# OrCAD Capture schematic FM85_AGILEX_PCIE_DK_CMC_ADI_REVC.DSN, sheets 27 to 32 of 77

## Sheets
27 QSFPDD IO: size B
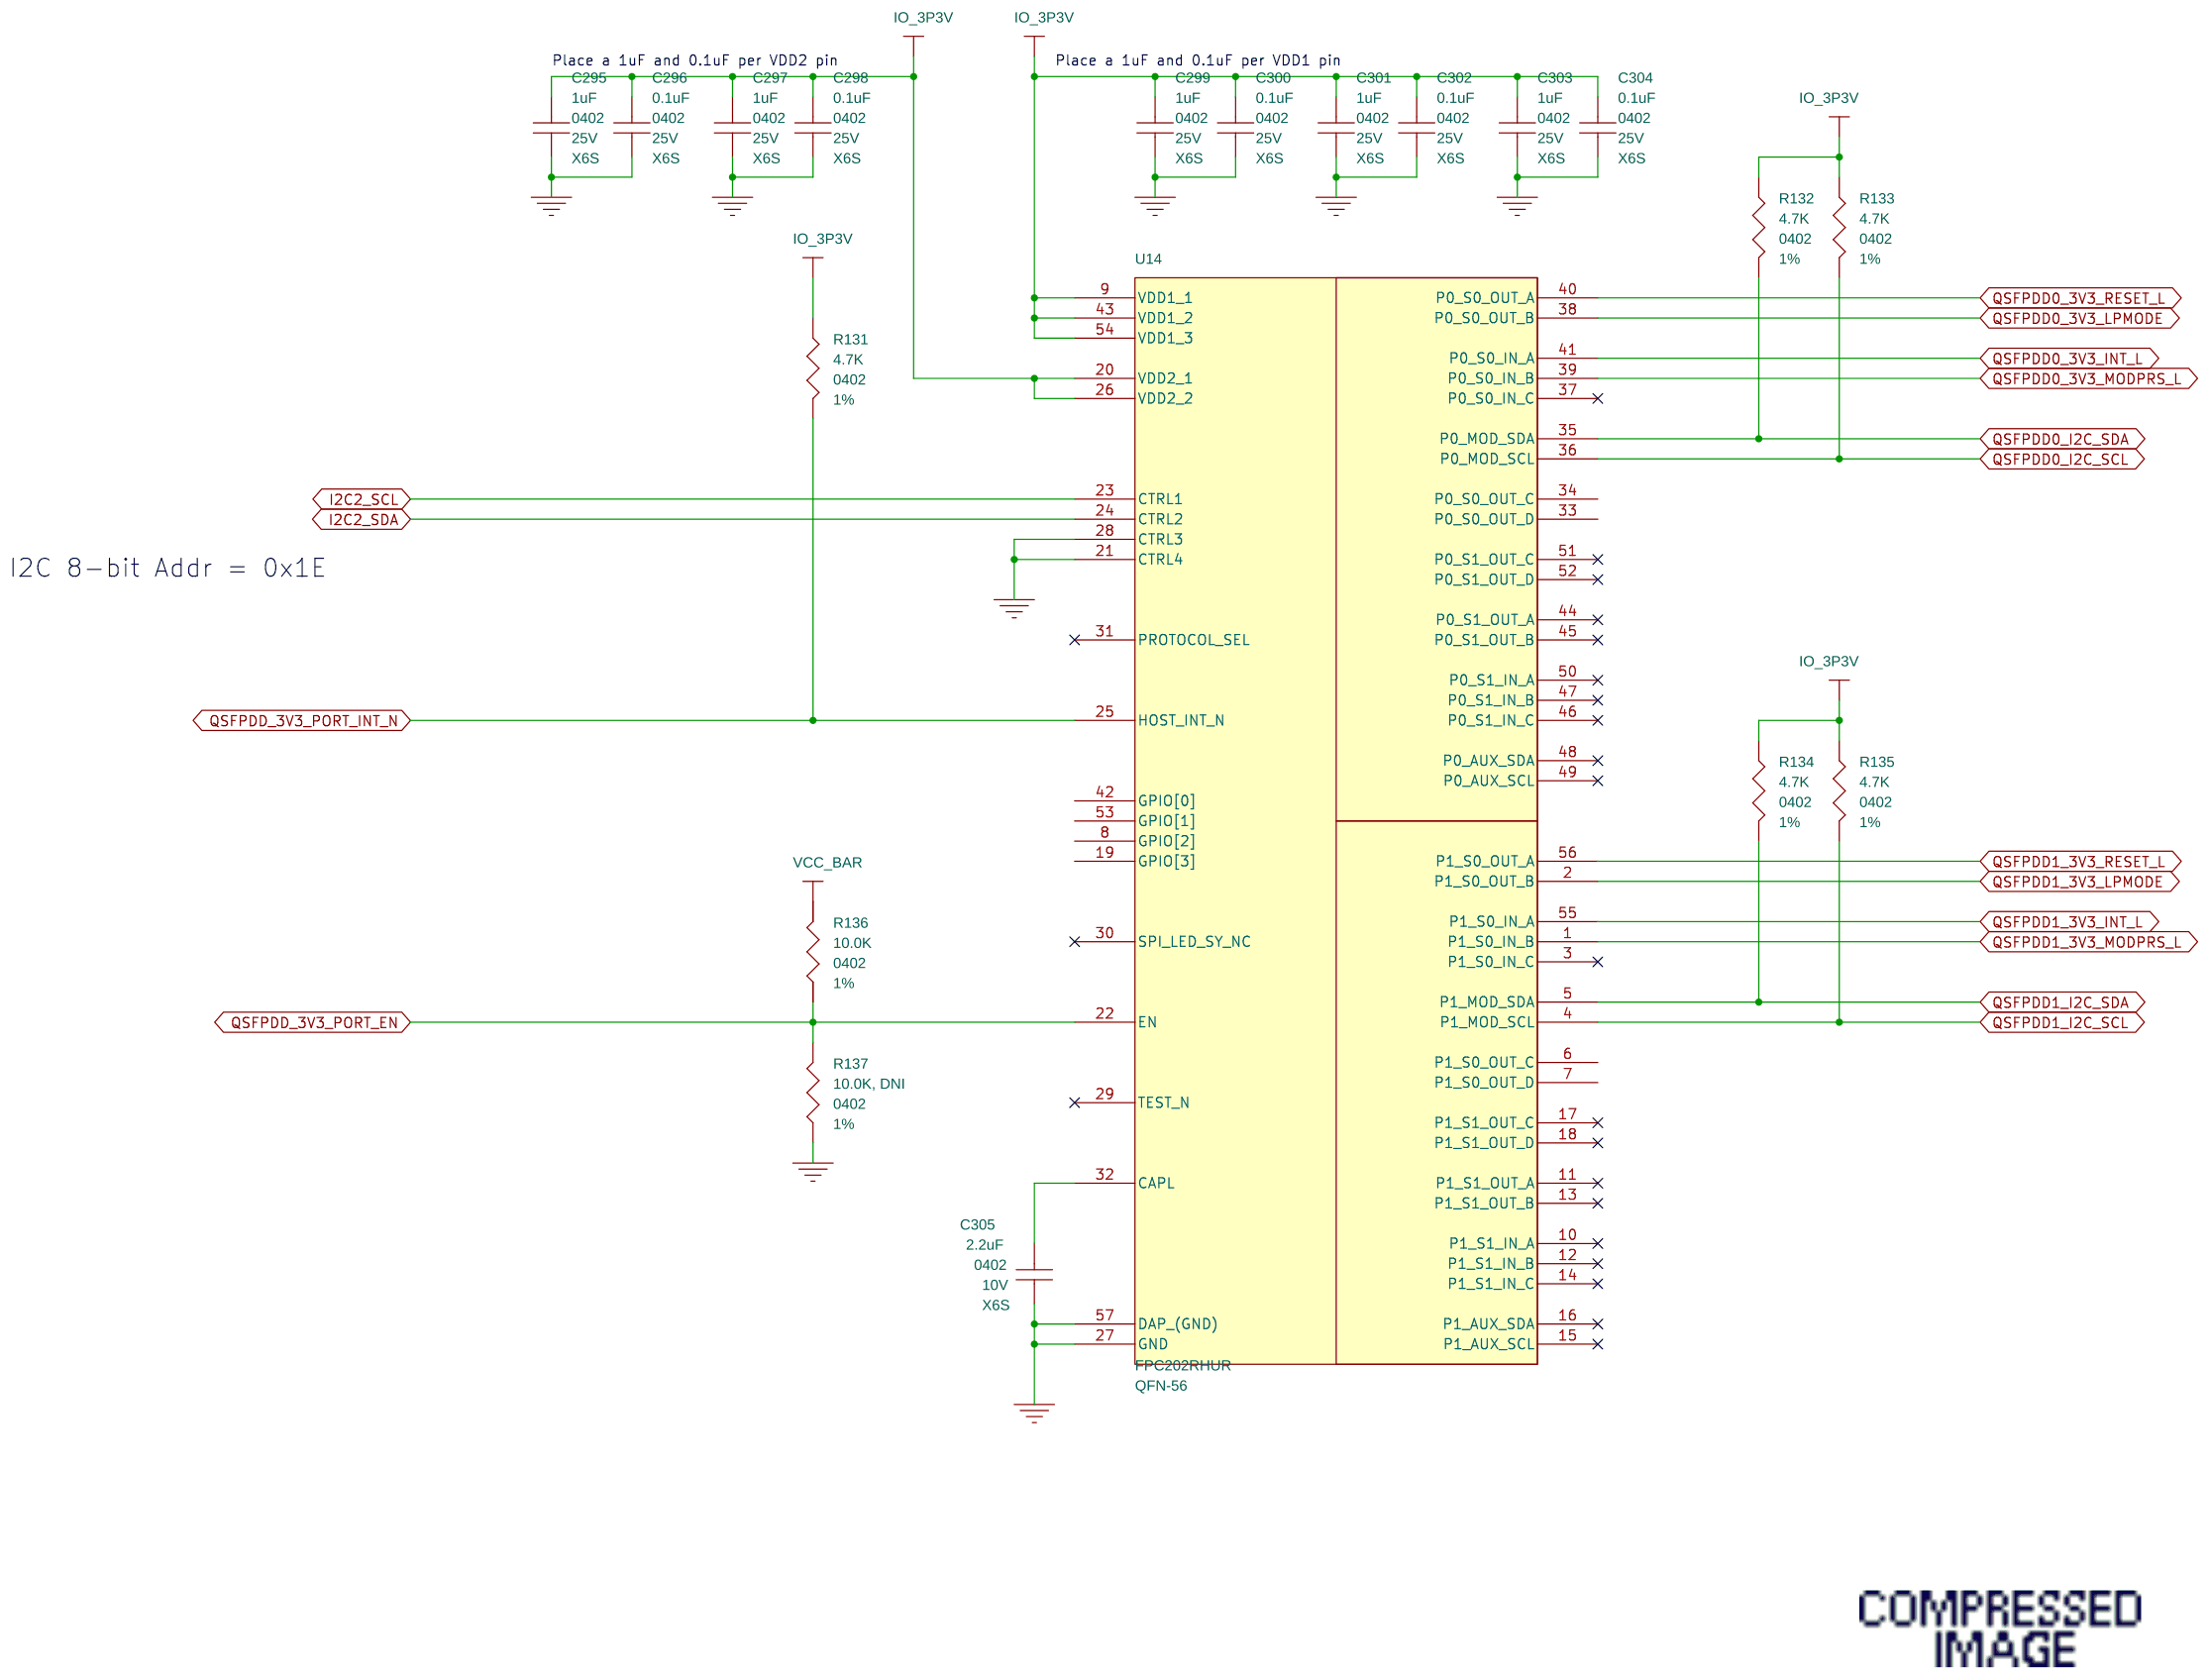
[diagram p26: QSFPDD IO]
28 FPGA BANK 12A: size B
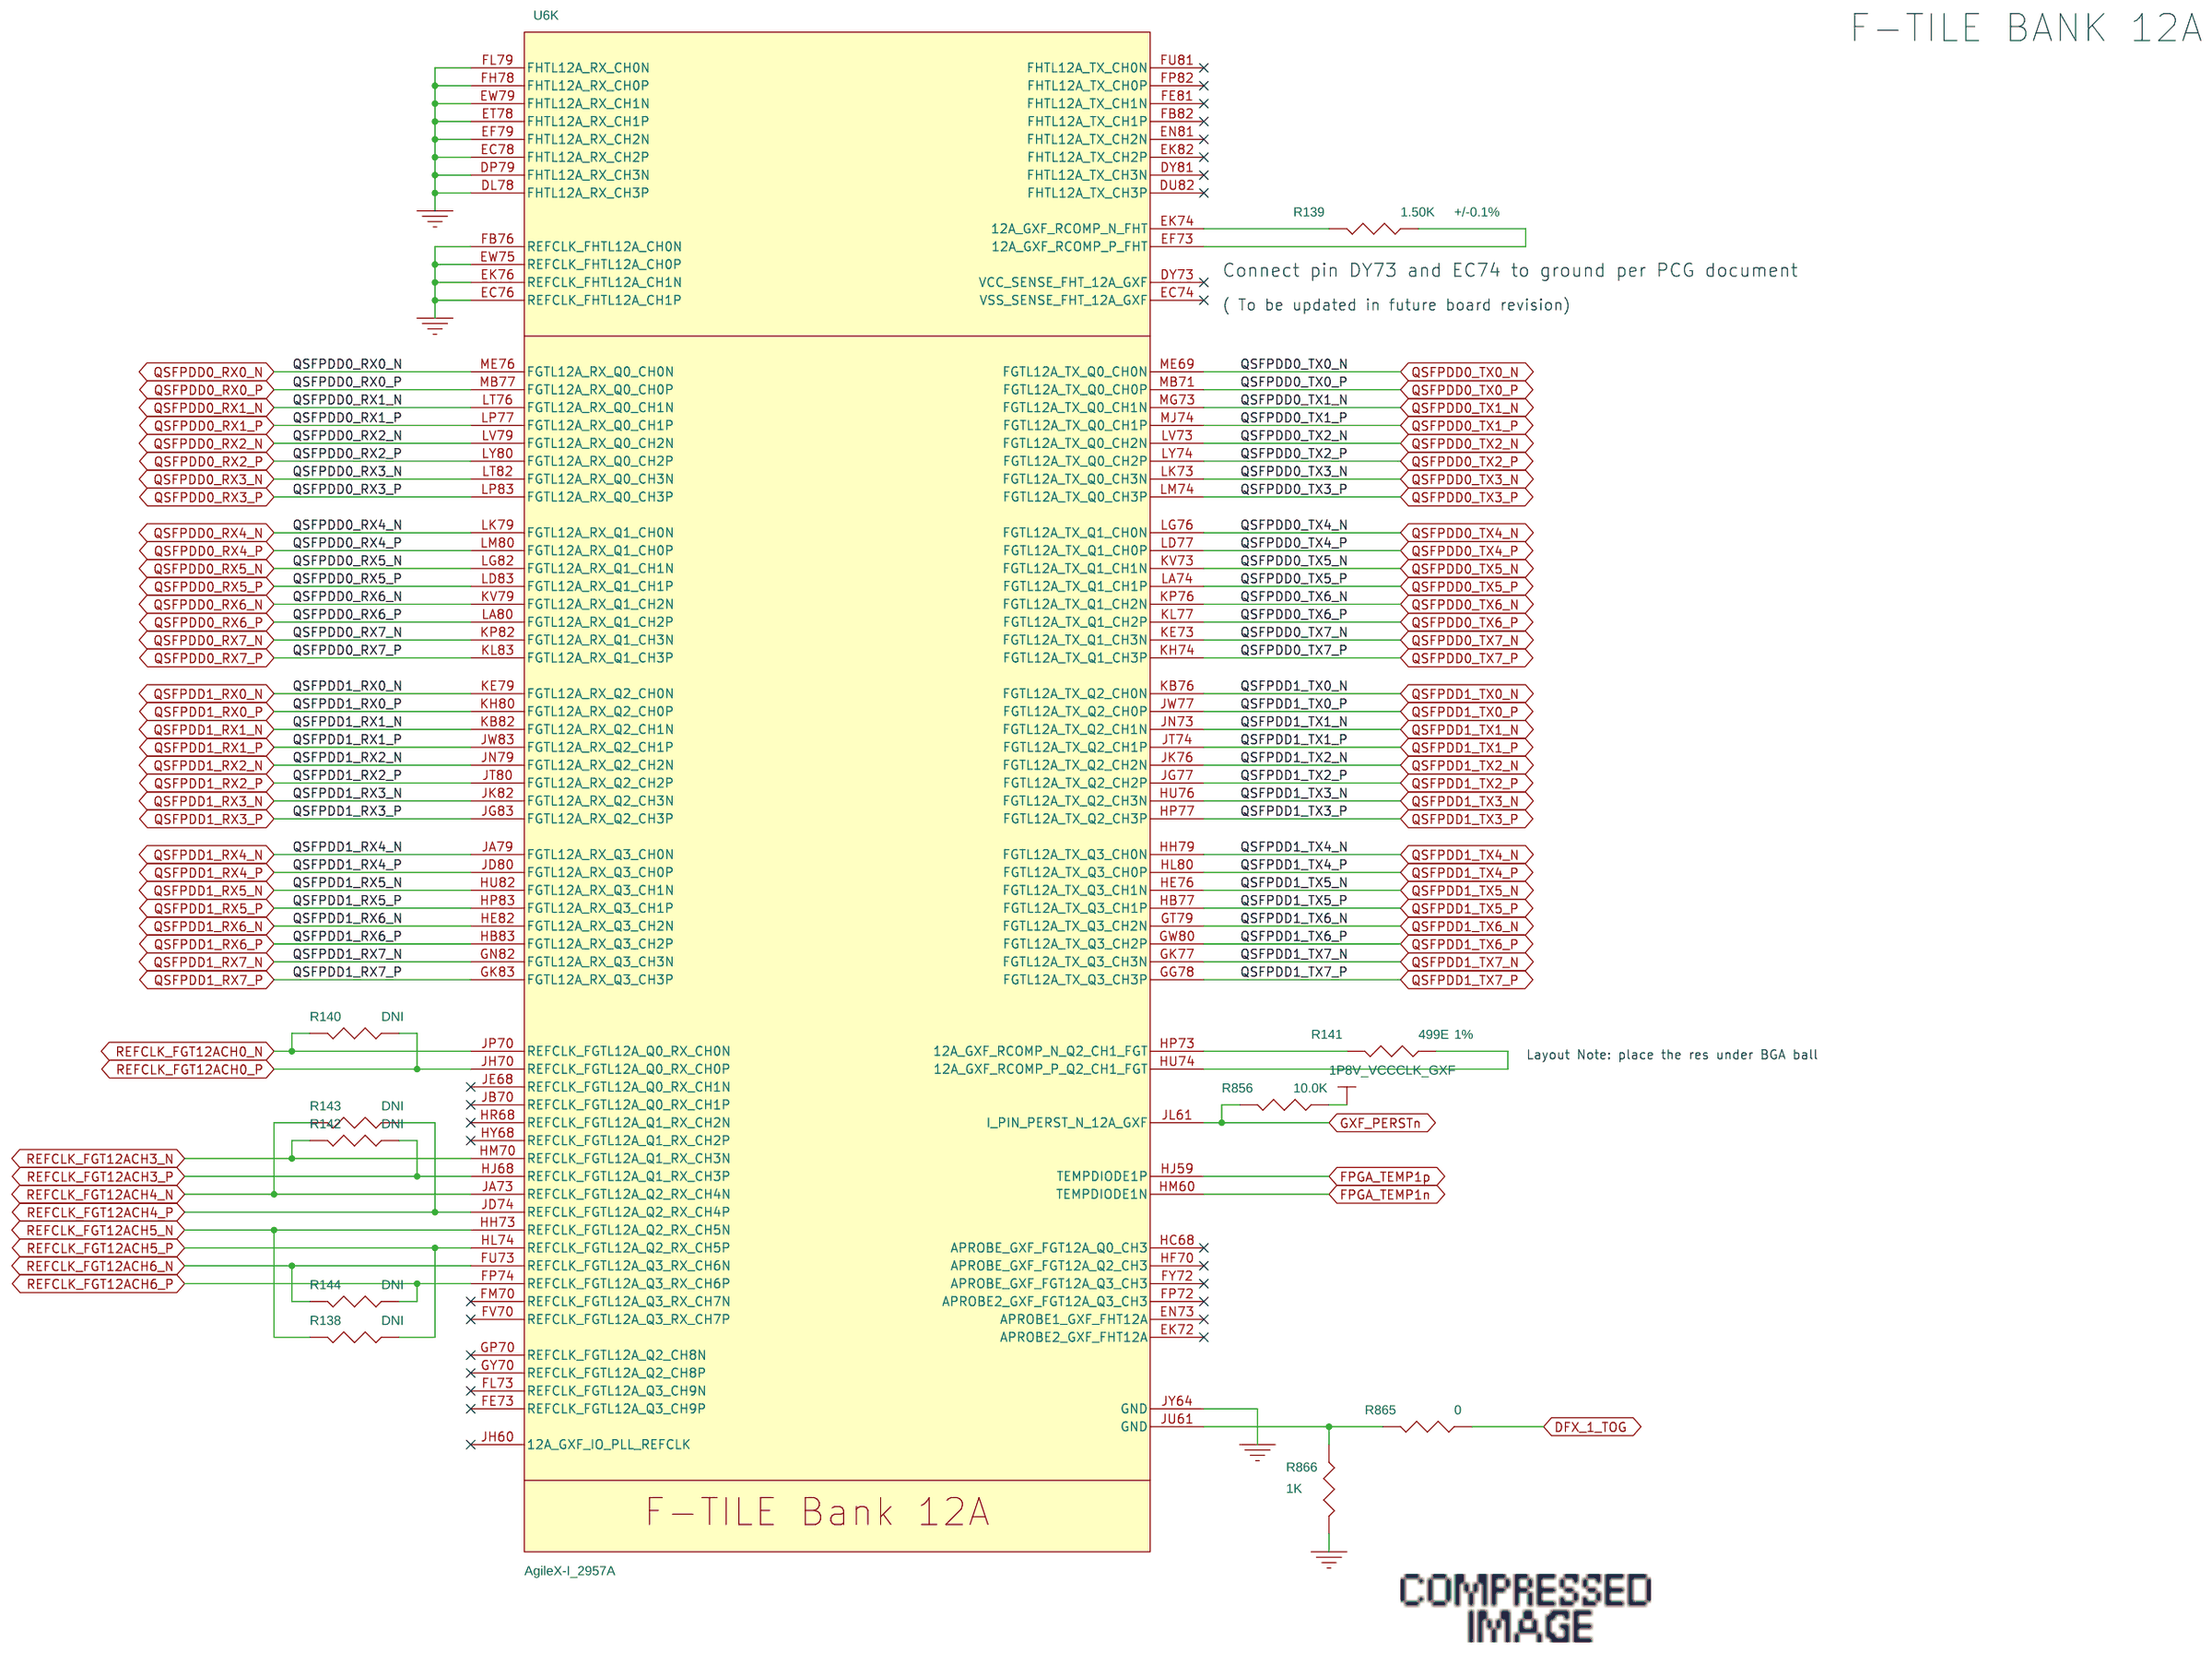
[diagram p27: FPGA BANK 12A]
29 FPGA BANK 12A DNU: size B
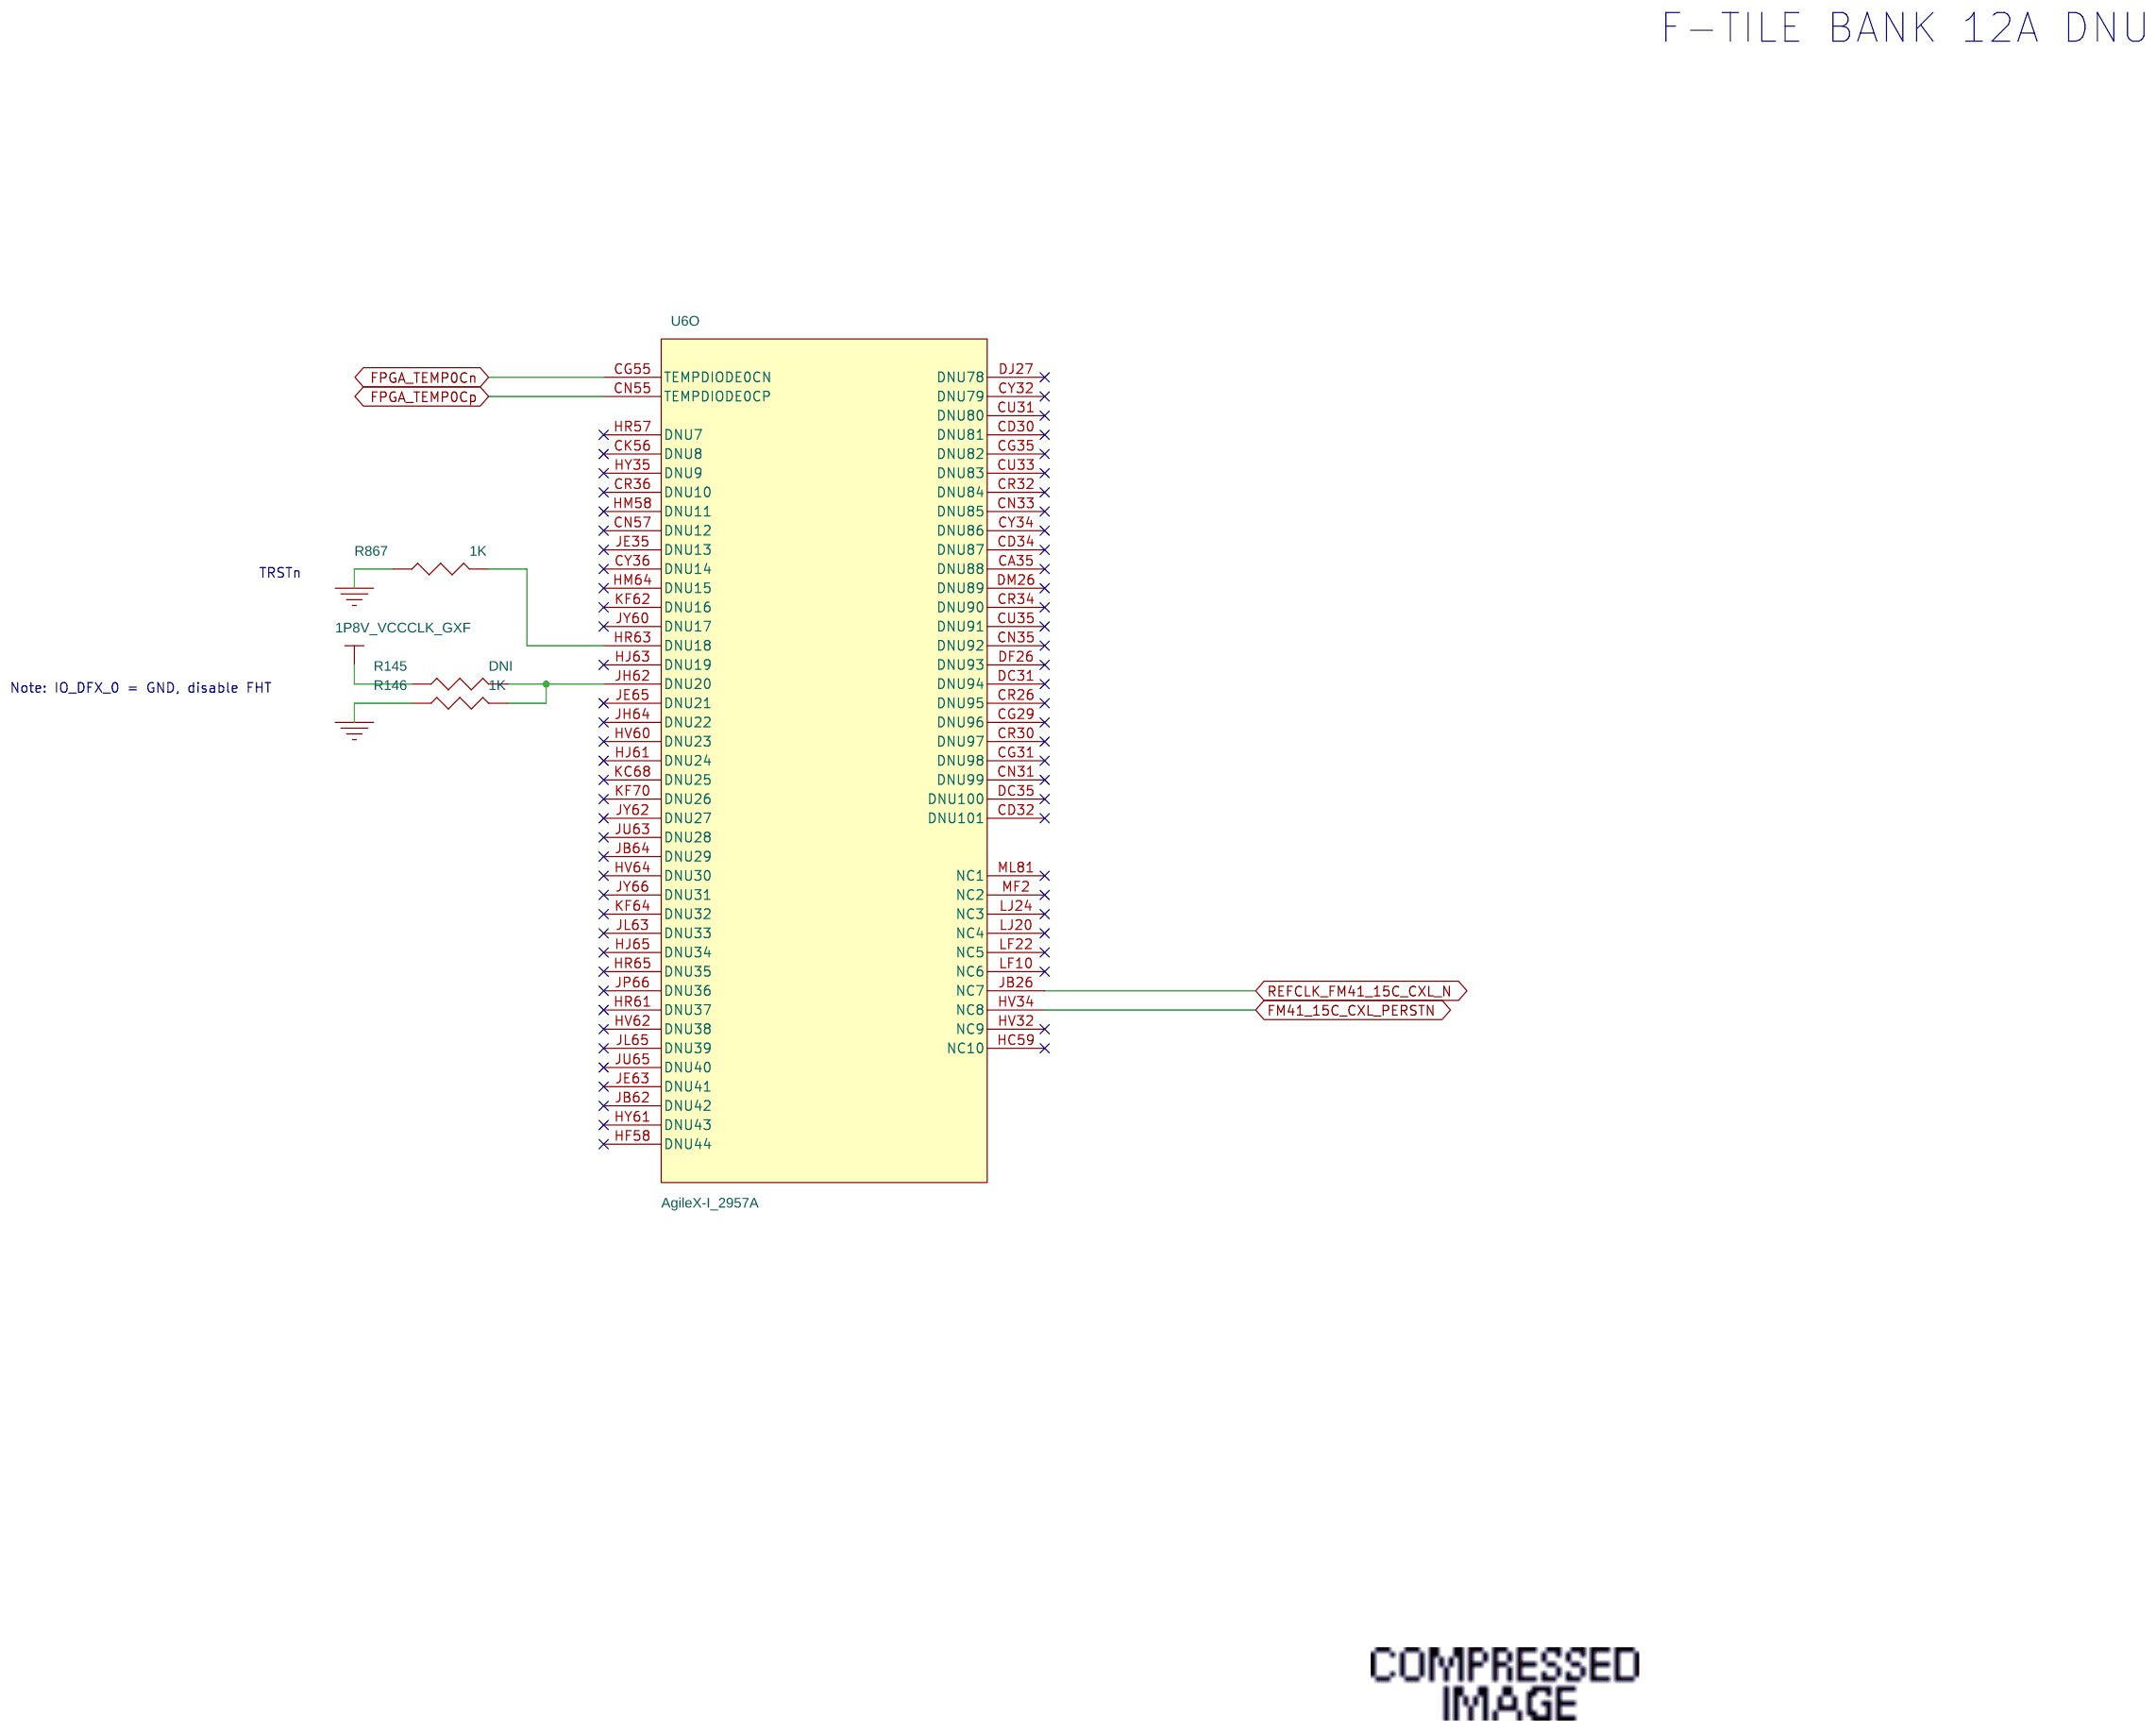
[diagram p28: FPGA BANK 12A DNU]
30 PCIe EP Edge Connector: size B
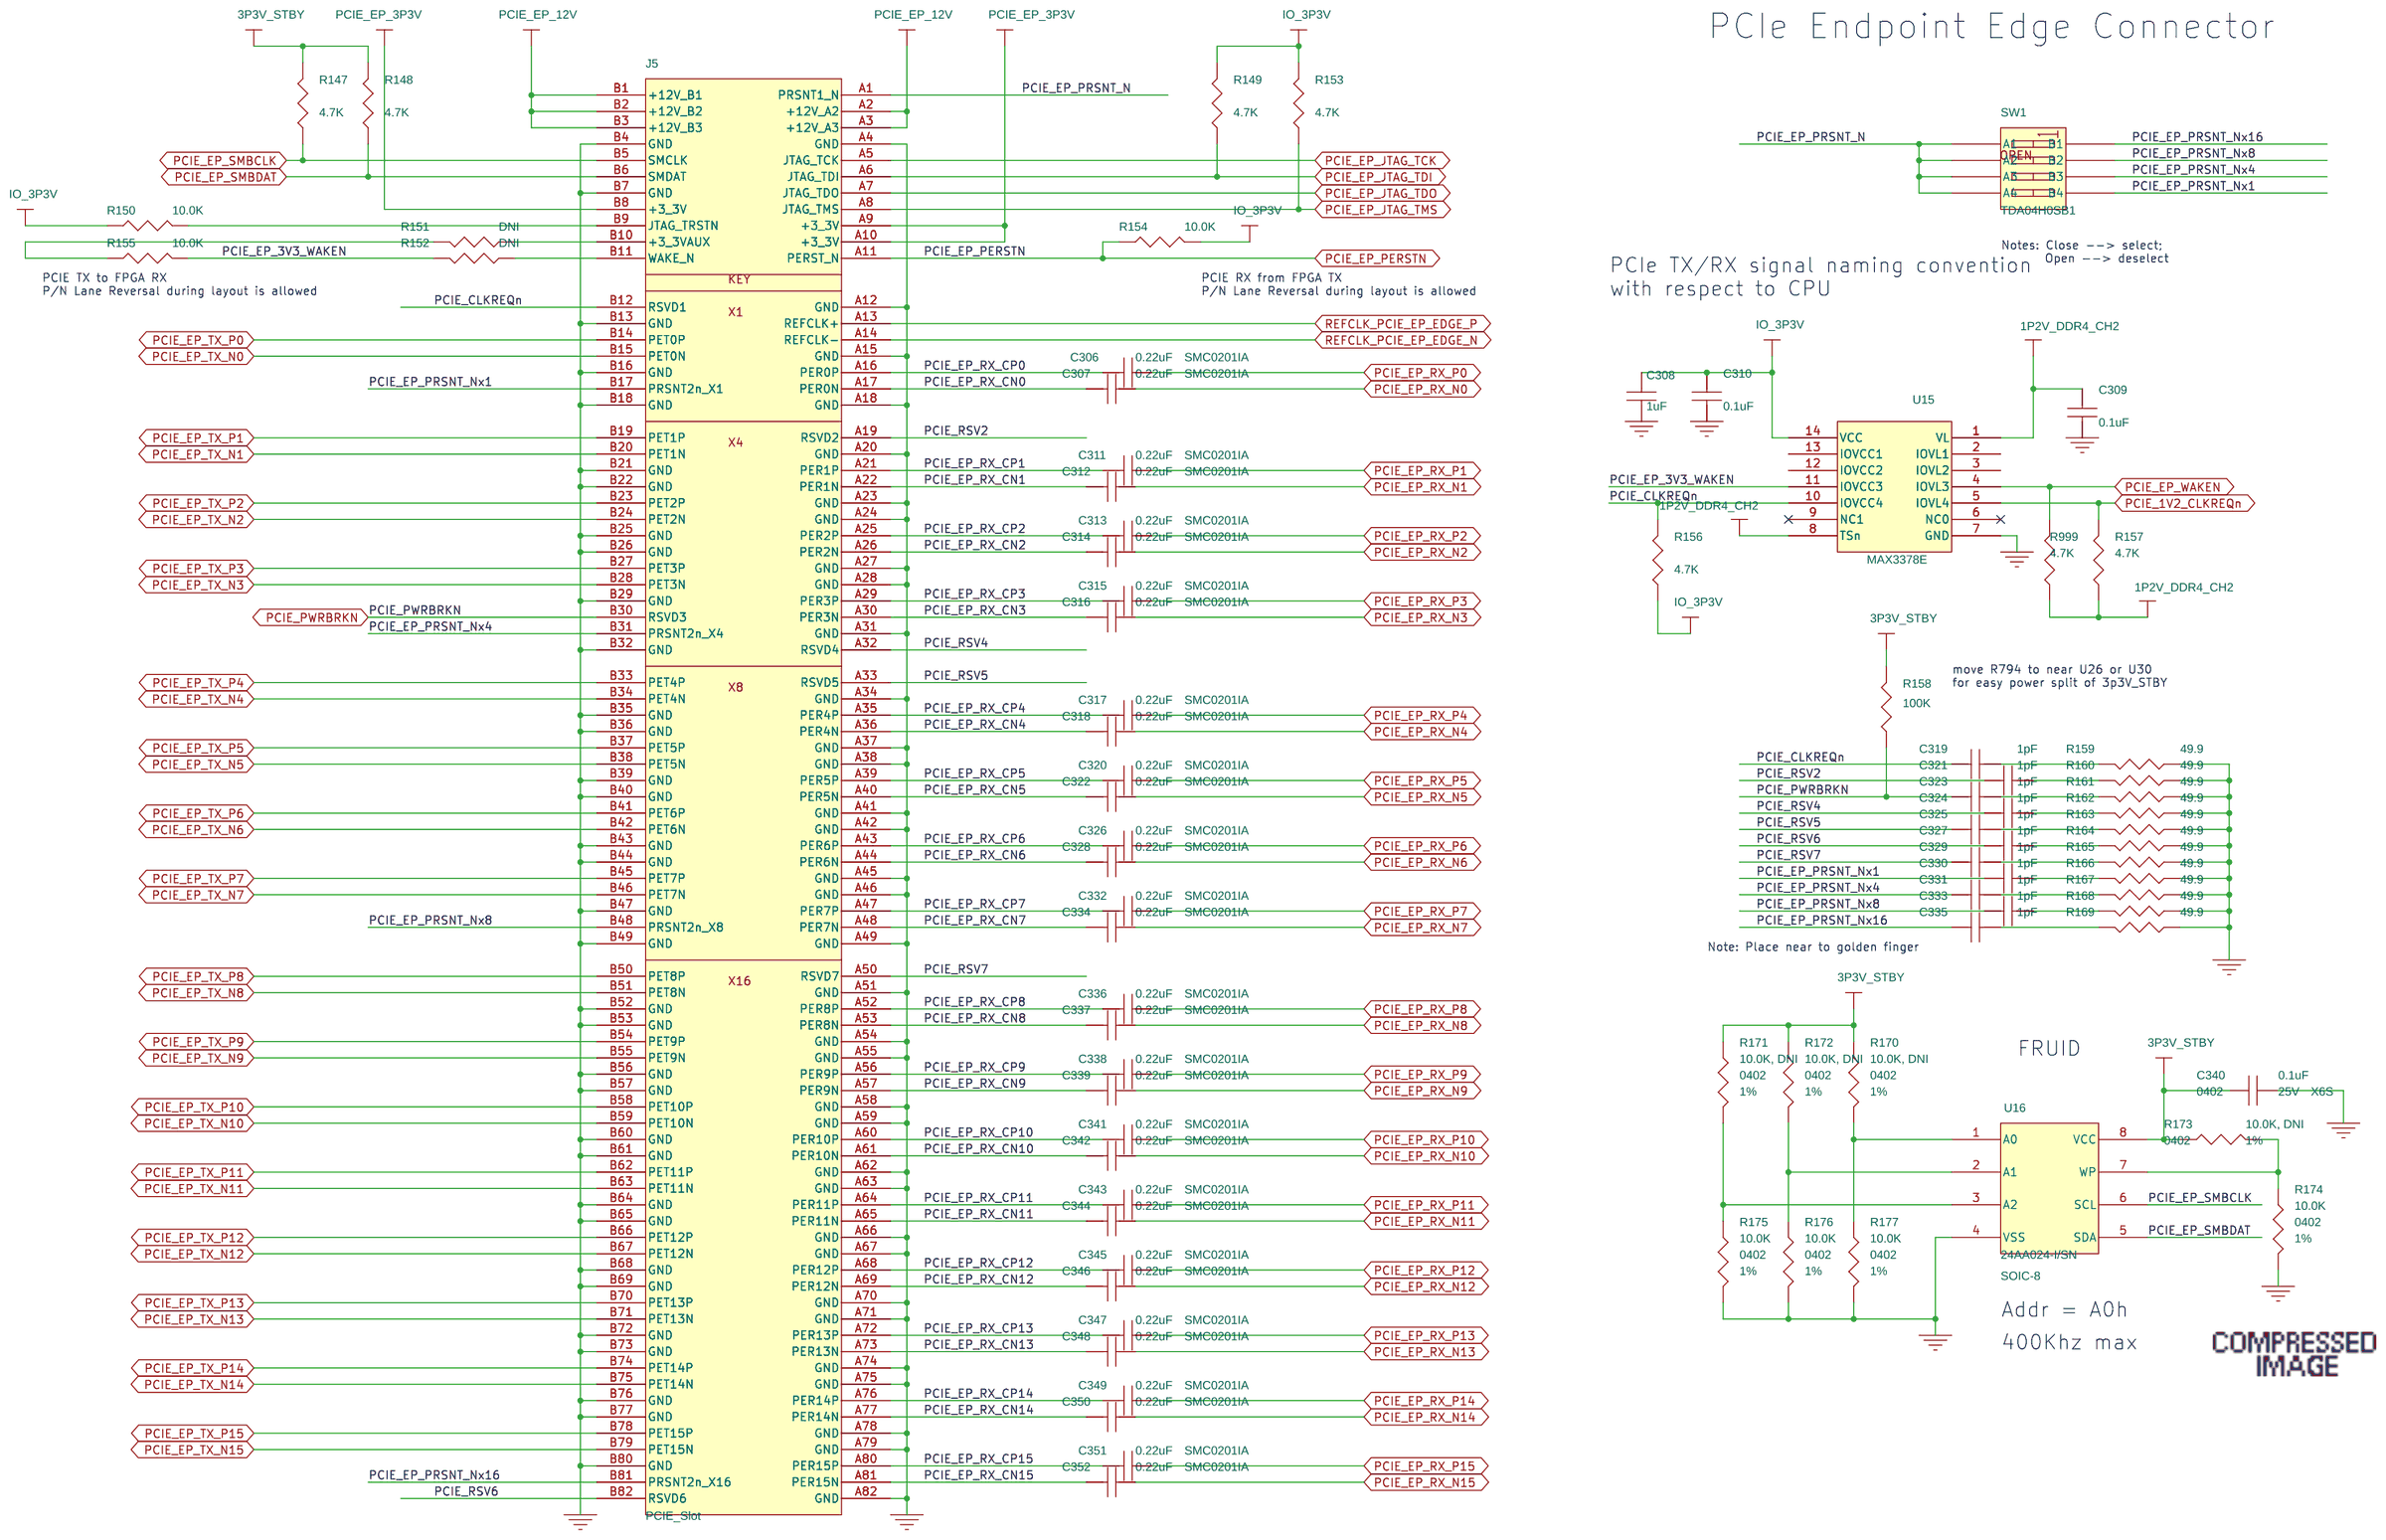
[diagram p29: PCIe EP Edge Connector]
31 FPGA BANK 14C: size B
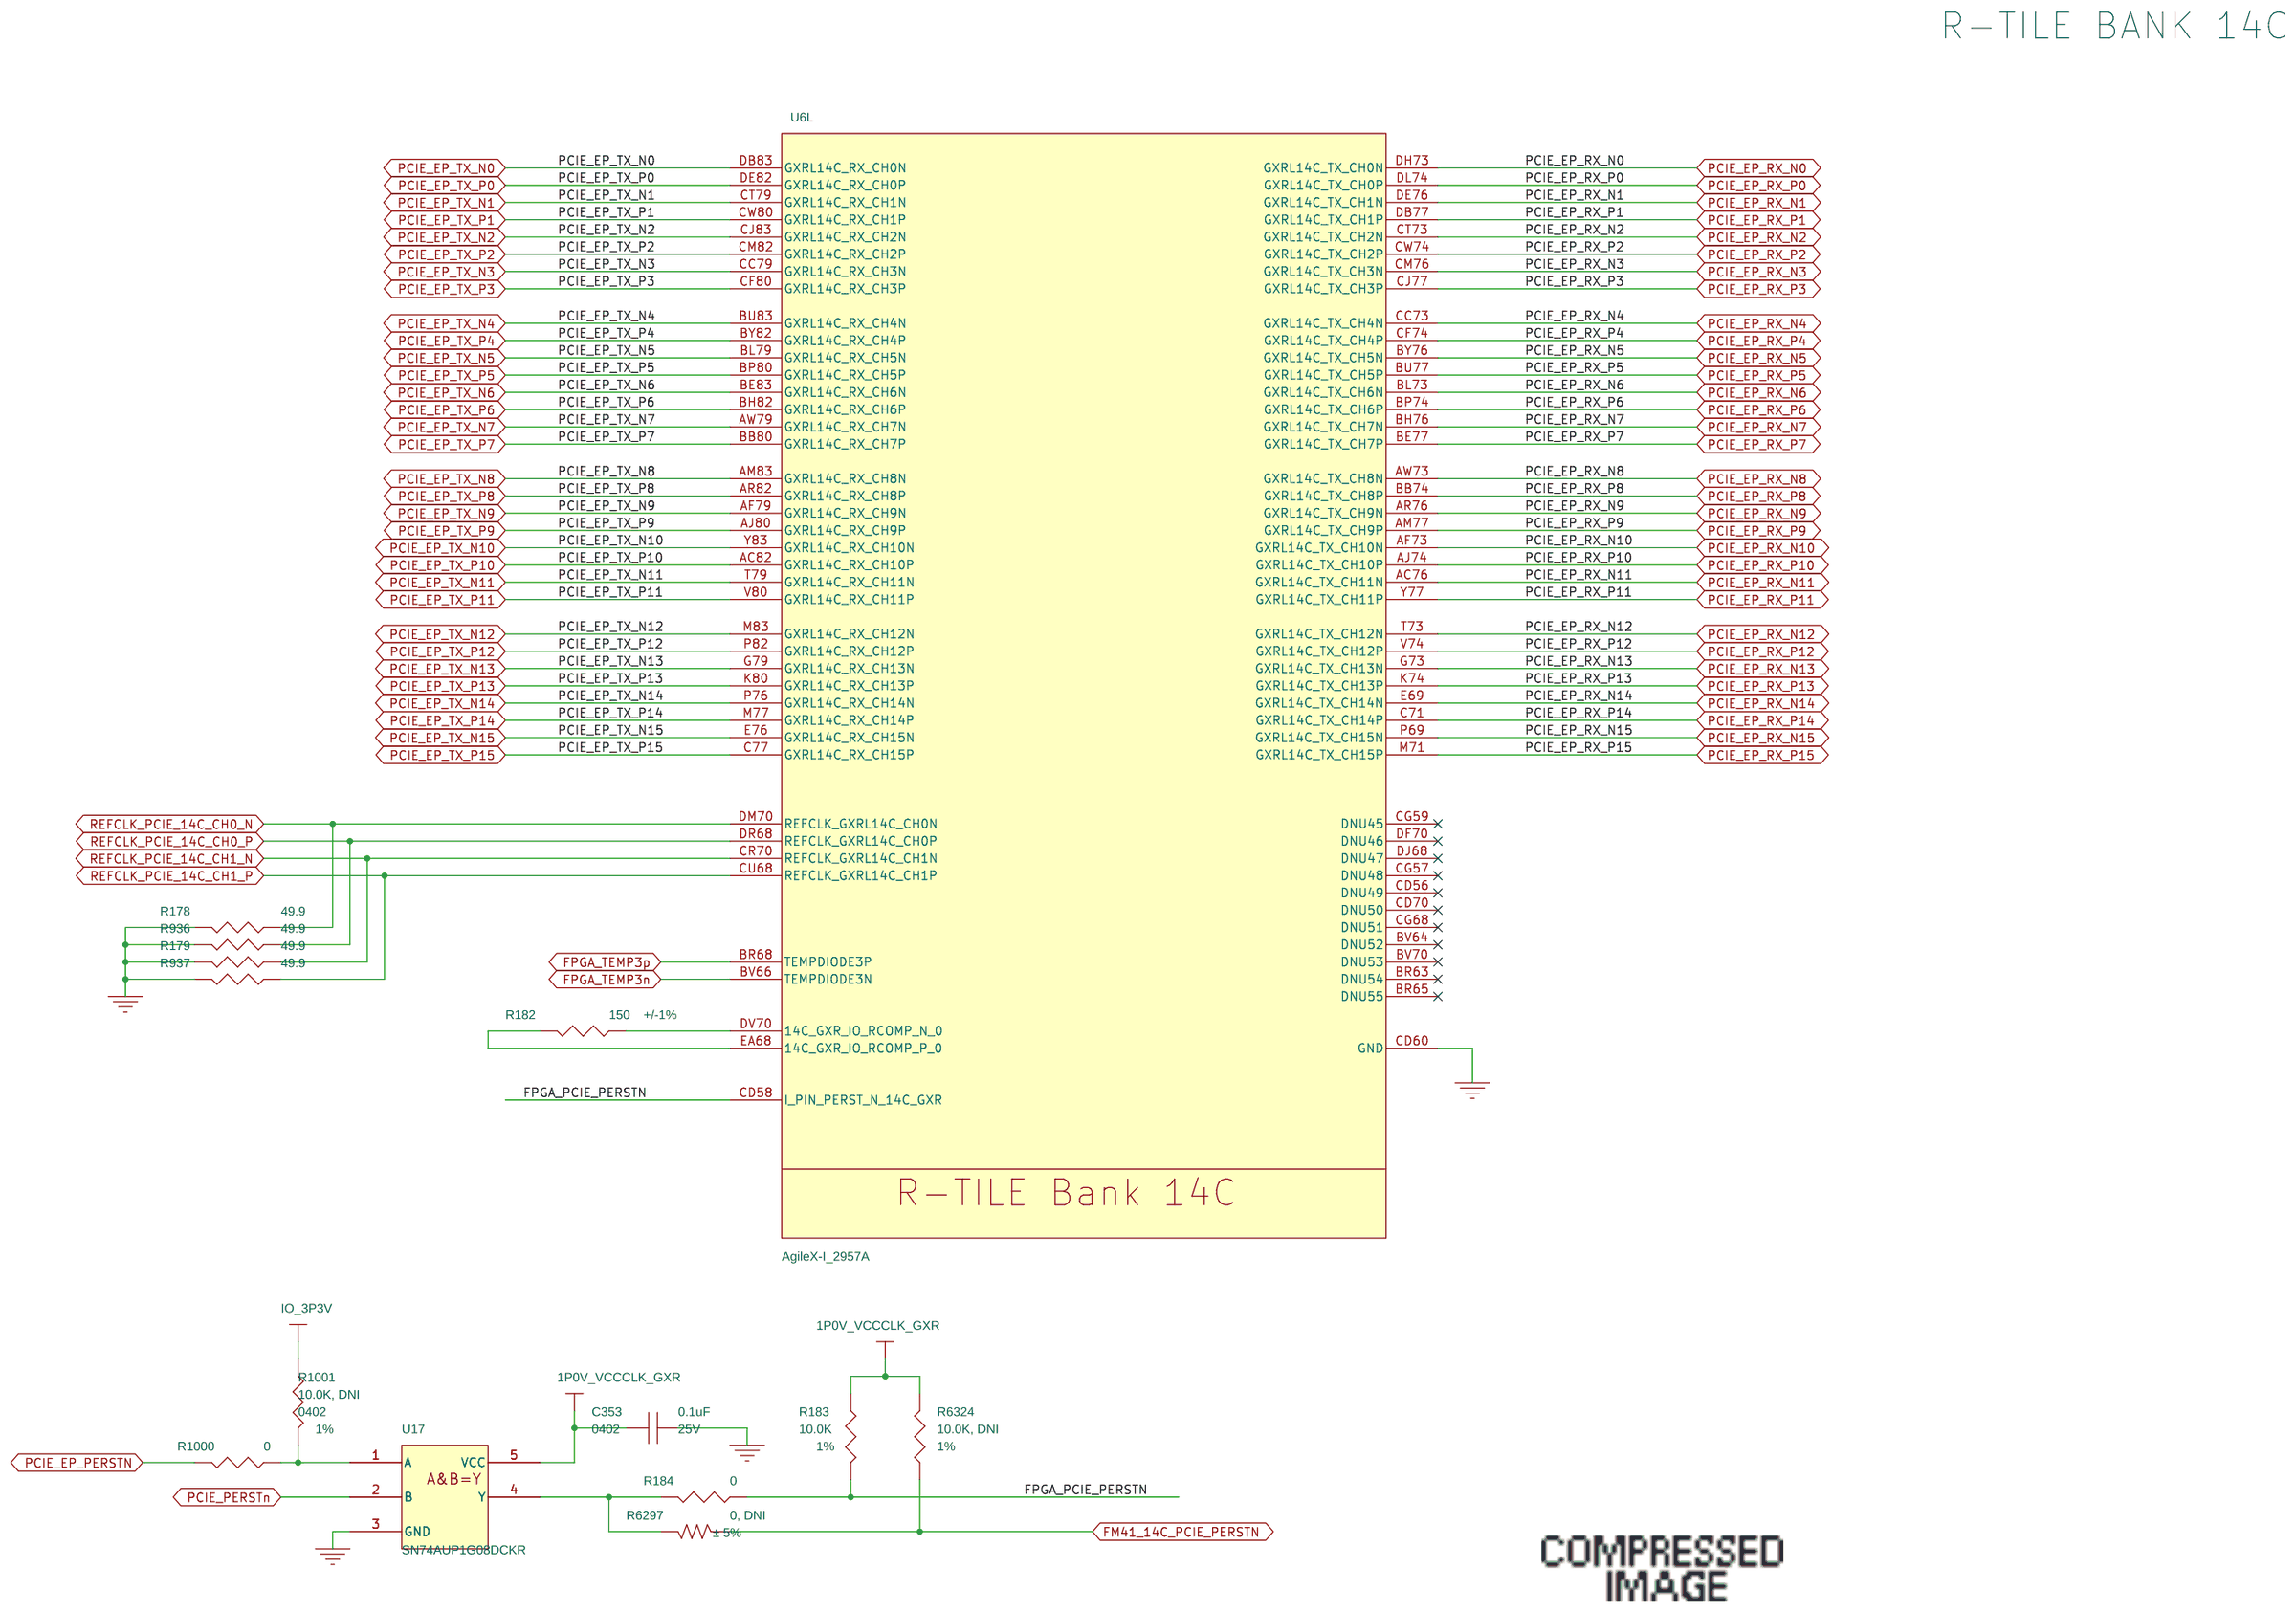
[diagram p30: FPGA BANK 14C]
32 CXL Connector: size B
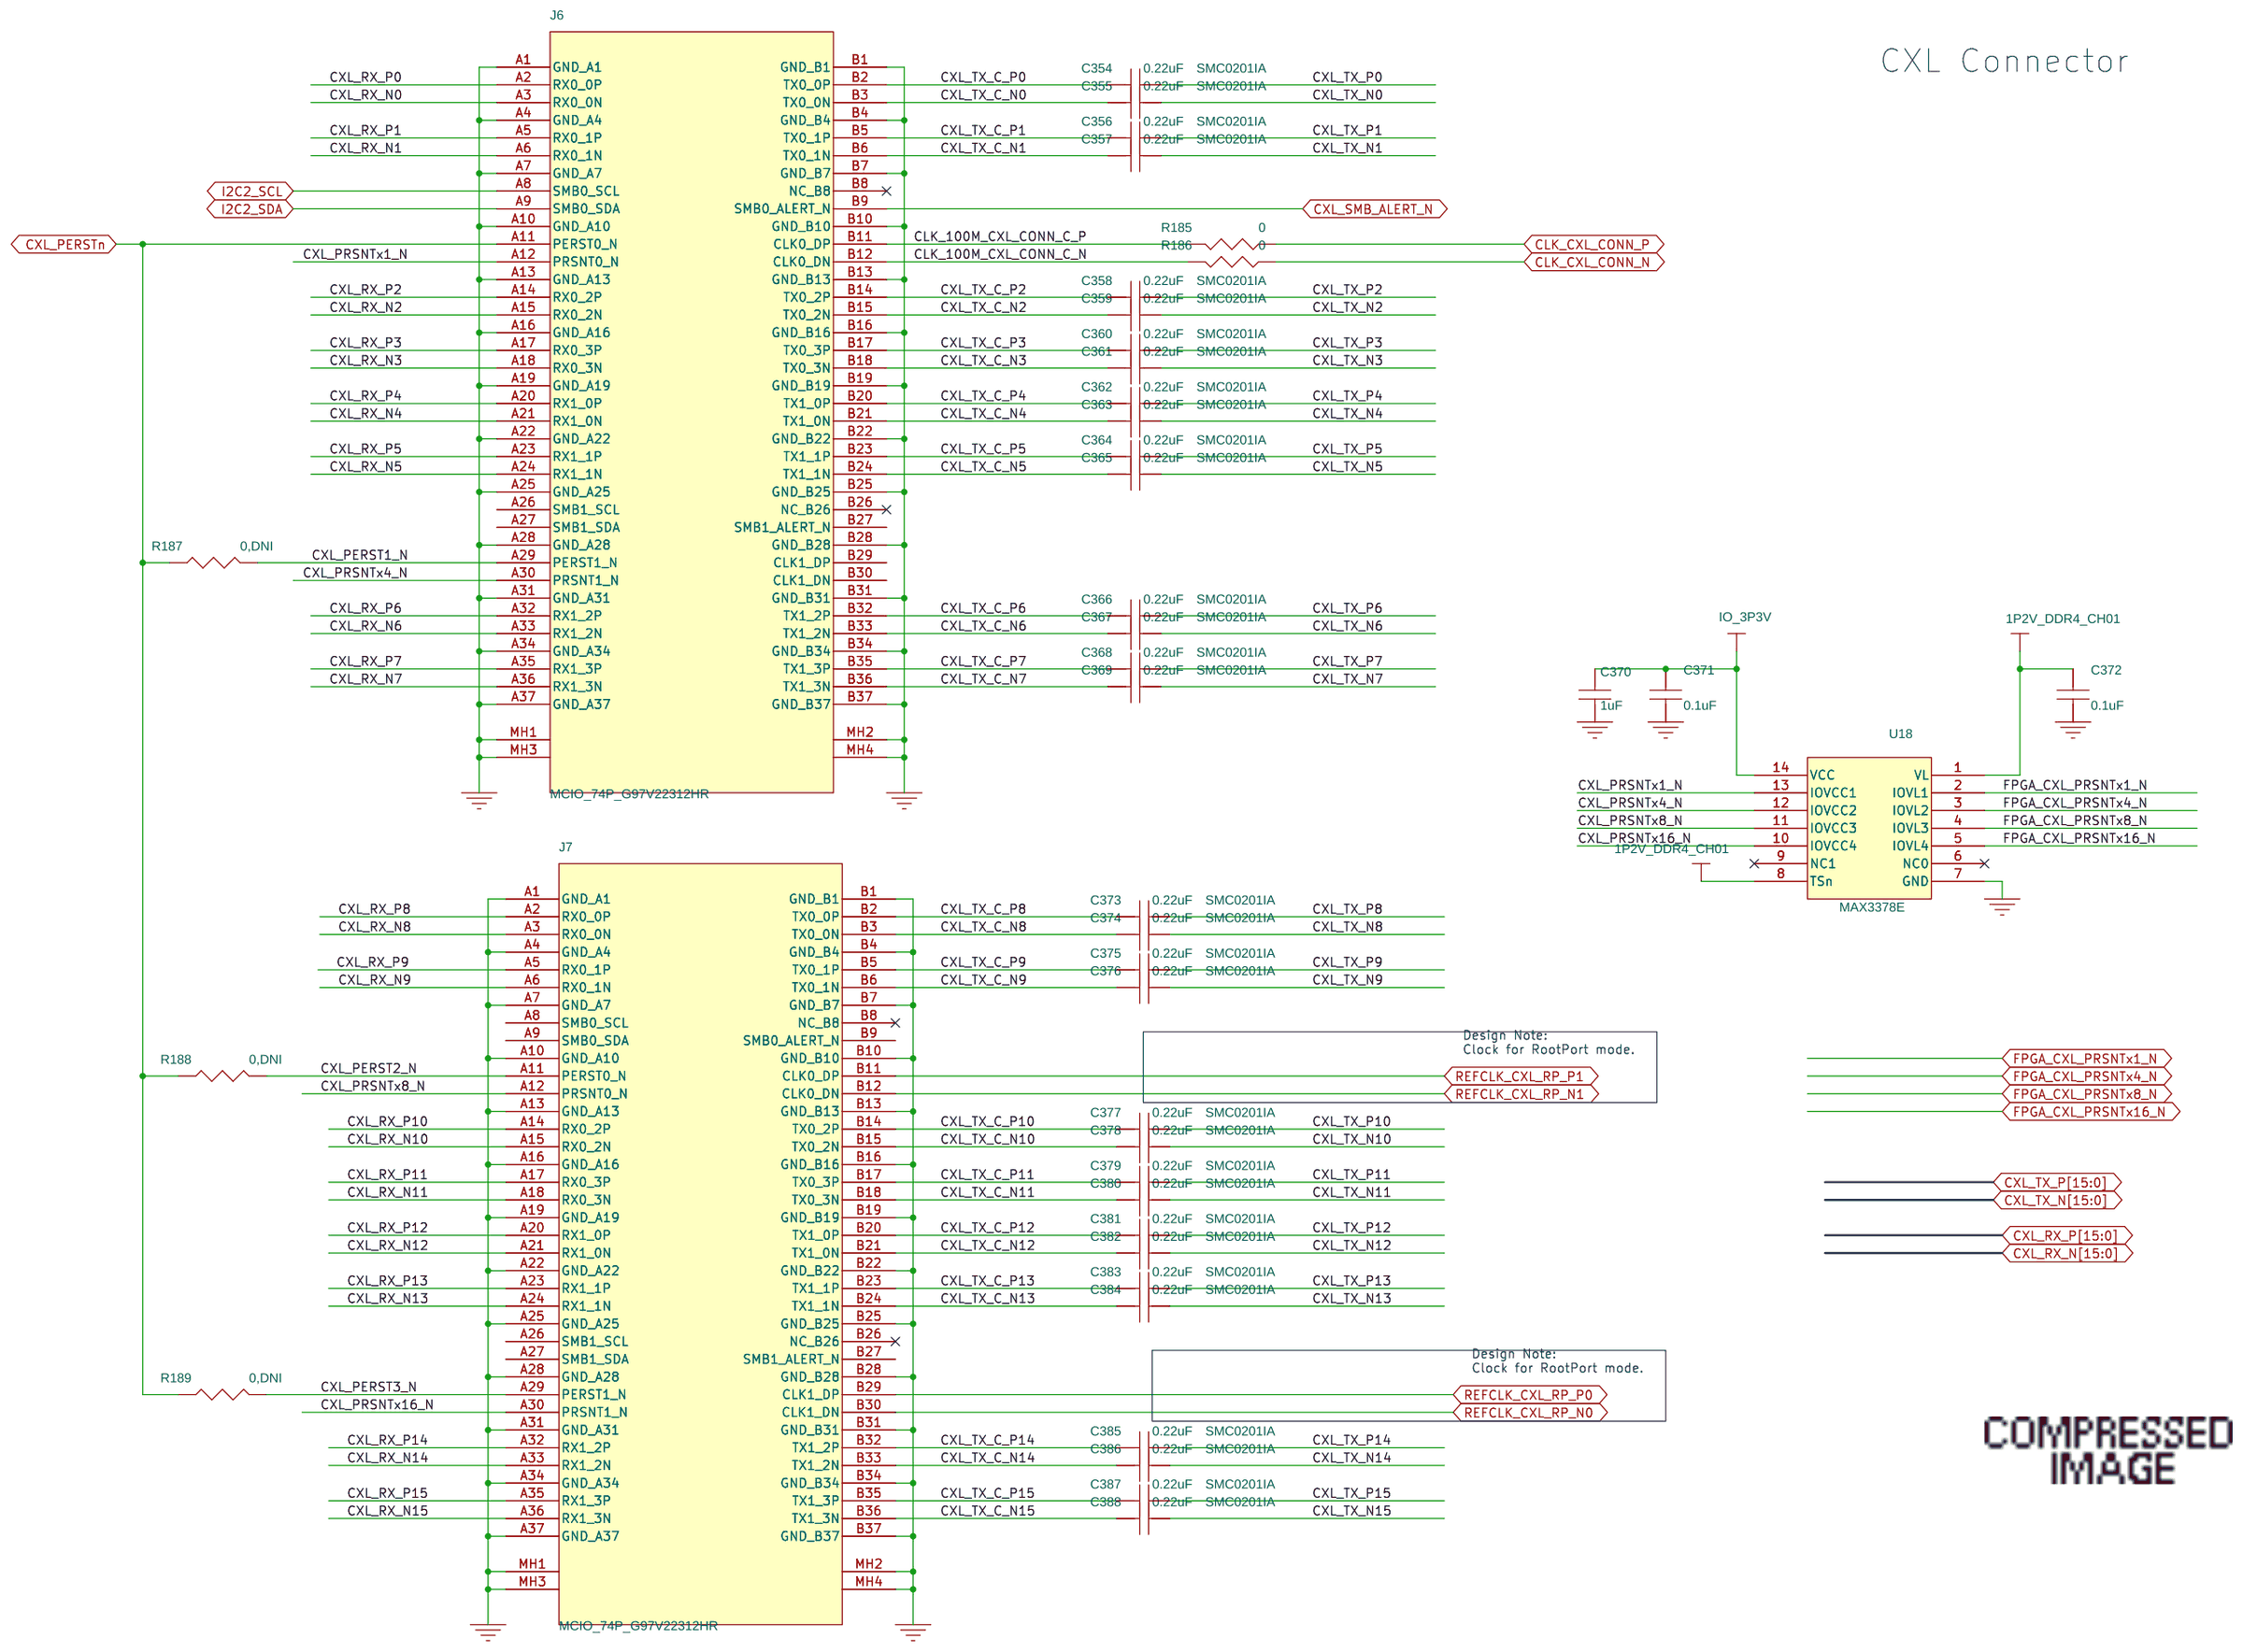
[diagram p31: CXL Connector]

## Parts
sheet CXL Connector
C354  0.22uF  [SMC0201IA]
C355  0.22uF  [SMC0201IA]
C356  0.22uF  [SMC0201IA]
C357  0.22uF  [SMC0201IA]
C358  0.22uF  [SMC0201IA]
C359  0.22uF  [SMC0201IA]
C360  0.22uF  [SMC0201IA]
C361  0.22uF  [SMC0201IA]
C362  0.22uF  [SMC0201IA]
C363  0.22uF  [SMC0201IA]
C364  0.22uF  [SMC0201IA]
C365  0.22uF  [SMC0201IA]
C366  0.22uF  [SMC0201IA]
C367  0.22uF  [SMC0201IA]
C368  0.22uF  [SMC0201IA]
C369  0.22uF  [SMC0201IA]
C370  1uF  [0402]
C371  0.1uF  [0402]
C372  0.1uF  [0402]
C373  0.22uF  [SMC0201IA]
C374  0.22uF  [SMC0201IA]
C375  0.22uF  [SMC0201IA]
C376  0.22uF  [SMC0201IA]
C377  0.22uF  [SMC0201IA]
C378  0.22uF  [SMC0201IA]
C379  0.22uF  [SMC0201IA]
C380  0.22uF  [SMC0201IA]
C381  0.22uF  [SMC0201IA]
C382  0.22uF  [SMC0201IA]
C383  0.22uF  [SMC0201IA]
C384  0.22uF  [SMC0201IA]
C385  0.22uF  [SMC0201IA]
C386  0.22uF  [SMC0201IA]
C387  0.22uF  [SMC0201IA]
C388  0.22uF  [SMC0201IA]
J6  MCIO_74P_G97V22312HR  [SCONN74_K64129002_PIP]
J7  MCIO_74P_G97V22312HR  [SCONN74_K64129002_PIP]
R185  0  [0402]
R186  0  [0402]
R187  0,DNI  [0402]
R188  0,DNI  [0402]
R189  0,DNI  [0402]
U18  MAX3378E  [TSSOP-14]
sheet FPGA BANK 2F
U6  AgileX-I_2957A  [fbga2957a_hex_p56x45]  (sections A,B,C,D,E,F,G,H,I,J,K,L,M,N,O,P,Q,R,S,T,U,V,W,X,Y,Z)
sheet FPGA BANK 12A DNU
R145  DNI  [0402]
R146  1K  [0402]
R867  1K  [0402]
sheet FPGA BANK 12A
R138  DNI  [0402]
R139  1.50K  [0402]
R140  DNI  [0402]
R141  499E  [0402]
R142  DNI  [0402]
R143  DNI  [0402]
R144  DNI  [0402]
R856  10.0K  [0402]
R865  0  [0402]
R866  1K  [0402]
sheet FPGA BANK 14C
C353  0.1uF  [0402]
R178  49.9  [0402]
R179  49.9  [0402]
R182  150  [0402]
R183  10.0K  [0402]
R184  0  [0402]
R936  49.9  [0402]
R937  49.9  [0402]
R1000  0  [0402]
R1001  10.0K, DNI  [0402]
R6297  0, DNI  [RESC1005X40L20L]
R6324  10.0K, DNI  [0402]
U17  SN74AUP1G08DCKR  [DCK]
sheet PCIe EP Edge Connector
C306  0.22uF  [SMC0201IA]
C307  0.22uF  [SMC0201IA]
C308  1uF  [0402]
C309  0.1uF  [0402]
C310  0.1uF  [0402]
C311  0.22uF  [SMC0201IA]
C312  0.22uF  [SMC0201IA]
C313  0.22uF  [SMC0201IA]
C314  0.22uF  [SMC0201IA]
C315  0.22uF  [SMC0201IA]
C316  0.22uF  [SMC0201IA]
C317  0.22uF  [SMC0201IA]
C318  0.22uF  [SMC0201IA]
C319  1pF  [0402]
C320  0.22uF  [SMC0201IA]
C321  1pF  [0402]
C322  0.22uF  [SMC0201IA]
C323  1pF  [0402]
C324  1pF  [0402]
C325  1pF  [0402]
C326  0.22uF  [SMC0201IA]
C327  1pF  [0402]
C328  0.22uF  [SMC0201IA]
C329  1pF  [0402]
C330  1pF  [0402]
C331  1pF  [0402]
C332  0.22uF  [SMC0201IA]
C333  1pF  [0402]
C334  0.22uF  [SMC0201IA]
C335  1pF  [0402]
C336  0.22uF  [SMC0201IA]
C337  0.22uF  [SMC0201IA]
C338  0.22uF  [SMC0201IA]
C339  0.22uF  [SMC0201IA]
C340  0.1uF  [0402]
C341  0.22uF  [SMC0201IA]
C342  0.22uF  [SMC0201IA]
C343  0.22uF  [SMC0201IA]
C344  0.22uF  [SMC0201IA]
C345  0.22uF  [SMC0201IA]
C346  0.22uF  [SMC0201IA]
C347  0.22uF  [SMC0201IA]
C348  0.22uF  [SMC0201IA]
C349  0.22uF  [SMC0201IA]
C350  0.22uF  [SMC0201IA]
C351  0.22uF  [SMC0201IA]
C352  0.22uF  [SMC0201IA]
J5  PCIE_Slot  [PCIX-16PORT]
R147  4.7K  [0402]
R148  4.7K  [0402]
R149  4.7K  [0402]
R150  10.0K  [0402]
R151  DNI  [0402]
R152  DNI  [0402]
R153  4.7K  [0402]
R154  10.0K  [0402]
R155  10.0K  [0402]
R156  4.7K  [0402]
R157  4.7K  [0402]
R158  100K  [0402]
R159  49.9  [0402]
R160  49.9  [0402]
R161  49.9  [0402]
R162  49.9  [0402]
R163  49.9  [0402]
R164  49.9  [0402]
R165  49.9  [0402]
R166  49.9  [0402]
R167  49.9  [0402]
R168  49.9  [0402]
R169  49.9  [0402]
R170  10.0K, DNI  [0402]
R171  10.0K, DNI  [0402]
R172  10.0K, DNI  [0402]
R173  10.0K, DNI  [0402]
R174  10.0K  [0402]
R175  10.0K  [0402]
R176  10.0K  [0402]
R177  10.0K  [0402]
R999  4.7K  [0402]
SW1  TDA04H0SB1  [DIPSWITCH_SMT_QUAD]
U15  MAX3378E  [TSSOP-14]
U16  24AA024-I/SN  [SOIC-8]
sheet QSFPDD IO
C295  1uF  [0402]
C296  0.1uF  [0402]
C297  1uF  [0402]
C298  0.1uF  [0402]
C299  1uF  [0402]
C300  0.1uF  [0402]
C301  1uF  [0402]
C302  0.1uF  [0402]
C303  1uF  [0402]
C304  0.1uF  [0402]
C305  2.2uF  [0402]
R131  4.7K  [0402]
R132  4.7K  [0402]
R133  4.7K  [0402]
R134  4.7K  [0402]
R135  4.7K  [0402]
R136  10.0K  [0402]
R137  10.0K, DNI  [0402]
U14  FPC202RHUR  [QFN-56]

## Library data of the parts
C306 C307 C311-C318 C320 C322 C326 C328 C332 C334 C336-C339 C341-C352 C354-C369 C373-C388 = CAP: CAP - CER, 0.22UF, 6.3V, 10%, X6S, 0201; Item Num: J19343-004; Manufacturer: Murata; Manufacturer Part Num: GRM033C80J224KE90D; Num Pins: 2; PART_SUBCLASS: CAPACITORS; RATED_VOLTAGE: 6.3V; TOLERANCE: +/-10%
C308 C370 = CAP: CAP - CER, 1uF, 10V, +/-10%, X5R, 0402; Item Num: G61001-001; Lead Free Status: Yes; Manufacturer: Murata; Manufacturer Part Num: GRM155R61A105KE15D; Num Pins: 2; Part Class: CAPACITORS; RoHS Compliant: Yes
C309 C310 C371 C372 = CAP: CAPC,  X7R, 0402, 0.1uF, 25V, ±20%; Dielectric: Y5V; Item Num: K13660-001; LIFECYCLE_PHASE: Active; Lead Free Status: Lead Free; MFR_LIFECYCLE: Active; Manufacturer: Murata; Manufacturer Part Num: GRM155R71E104KE14D; Num Pins: 2; PART_SUBCLASS: CAPACITORS; Part Class: CAPACITORS; RATED_VOLTAGE: 25V; RoHS Compliant: RoHS Compliant; Tolerance: +80%/-20%
J6 J7 = CON_MCIO_74P_G42V12312HR: MCIO x8 Conn, 74p, G97V22312HR; Item Num: K64129-002; Manufacturer: Amphenol; Manufacturer Part Num: G97V22312HR
R185 R186 = RESISTOR: RES D,0402,0.00 OHM,5.00%,1/16W; Agile IPN: P02-14020R; Item Num: A93549-001; Manufacturer: Panasonic; Manufacturer Part Num: ERJ-2GE0R00X; Num Pins: 2; Part Class: RESISTORS; Tolerance: 5%
R187-R189 = RESISTOR: RES D,0402,0.00 OHM,5.00%,1/16W; Agile IPN: P02-14020R; Item Num: A93549-001; Manufacturer: Yageo; Manufacturer Part Num: RC0402JR-070RL; Num Pins: 2; Part Class: RESISTORS
U15 U18 = MAX3378E_0: IC - QUAD LOW-VOLTAGE LEVEL TRANSLATOR, +/- 15KV, ESD-PROTECTED, 1UA, 16MBPS; Item Num: C34337-001; Manufacturer: Maxim; Manufacturer Part Num: MAX3378EEUD
U6 = AgileX-I_2957A: Item Num: 99C7VA
R145 R146 R866 R867 = RESISTOR: RES,1.00K OHMS,1.0%,1/16W,0402; Item Num: G60609-021; Lead Free Status: No; Manufacturer: Panasonic; Manufacturer Part Num: ERJ-2RKF1001X; Num Pins: 2; Part Class: Resistors
R138 R140 R142-R144 = RESISTOR: RES,100 OHMS,1.0%,1/16W,0402; Item Num: A36092-043; Lead Free Status: No; Manufacturer: Panasonic; Manufacturer Part Num: ERJ-2RKF1000X; Manufacturer's Part No.: ERJ-2RKF1000X; Num Pins: 2; Part Class: RESISTORS; Price: 0; RoHS Compliant: Yes
R139 = RESISTOR: RES,1.50 kOHMS,0.1%,1/16W,0402; Item Num: J84875-001; Manufacturer: Panasonic; Manufacturer Part Num: ERA-2AEB152X; Num Pins: 2; Part Class: RESISTORS; TOLERANCE: +/-0.1%
R141 = RESISTOR: RES,499 OHMS,1.0%,1/16W,0402; Item Num: A93548-094; Manufacturer: Yageo; Manufacturer Part Num: RC0402FR-07499RL; Num Pins: 2; Part Class: RESISTORS; TOLERANCE: 1%
R856 = RESISTOR: RES,10.0K OHMS,1.0%,1/16W, 0402; AGILE_LINK: http://sj-agile9app/Agile/PLMServlet?action=OpenEmailObject&classid=10000&objid=146548997; Item Num: G60609-021; LIFECYCLE_PHASE: Active; Lead Free Status: No; MFR_LIFECYCLE: Active; Manufacturer: Panasonic; Manufacturer Part Num: ERJ-2RKF1002X; Num Pins: 2; PART_SUBCLASS: RESISTORS; POWER: 1/16W; RoHS Compliant: Yes; TOLERANCE: +/-1%
R184 R865 R1000 = RESISTOR: RES ZERO OHM 1/16W 5% 0402 SMD; Agile IPN: P02-14020R; Altera Part No.: P02-14020R; Item Num: H30887-001; Lead Free Status: No; Manufacturer: Panasonic; Manufacturer Part Num: ERJ-2GE0R00X; Num Pins: 2; Part Class: RESISTORS; RoHS Compliant: Yes; Tolerance: 5%
C340 C353 = CAP: CAPC,  X7R, 0402, 0.1uF, 25V, ±20%; Dielectric: X6S; Item Num: K13660-001; LIFECYCLE_PHASE: Active; Lead Free Status: Lead Free; Manufacturer: Murata; Manufacturer Part Num: GRM155R71E104KE14D; Num Pins: 2; Part Class: CAPACITORS; RATED_VOLTAGE: 25V; RoHS Compliant: RoHS Compliant; Tolerance: 10%
R159-R169 R178 R179 R936 R937 = RESISTOR: RES, 49.9 OHMS, 1%, 1/16W, 0402; Item Num: K16545-001; Lead Free Status: Yes; Manufacturer: NIC Components Corp.; Manufacturer Part Num: NRC04F49R9TRF; Num Pins: 2; Part Class: Resistors; Price: 0
R182 = RESISTOR: RES,150 OHMS,1.0%,1/16W,0402; Item Num: G60609-012; Manufacturer: Yageo; Manufacturer Part Num: RC0402FR-07150RL; Num Pins: 2; Part Class: RESISTORS; TOLERANCE: +/-1%
R136 R137 R170-R177 R183 R1001 R6324 = RESISTOR: RES,10.0K OHMS,1.0%,1/16W, 0402; AGILE_LINK: http://sj-agile9app/Agile/PLMServlet?action=OpenEmailObject&classid=10000&objid=146548997; Item Num: K28115-001; LIFECYCLE_PHASE: Active; Lead Free Status: No; MFR_LIFECYCLE: Active; Manufacturer: Panasonic; Manufacturer Part Num: ERJ-2RKF1002X; Num Pins: 2; PART_SUBCLASS: RESISTORS; POWER: 1/16W; RESISTANCE: 10K; RoHS Compliant: Yes; TOLERANCE: 1%
R6297 = Resistor,_0402_0: RES D,0402,0.00 OHM,5.00%,1/16W; Agile Part Number: 02495; Item Num: A93549-001; Manufacturer: YAGEO CORP.; Manufacturer Part Num: ERJ-2GE0R00X; Package: 0402; Part Number: ERJ-2GE0R00X; Tolerance: ± 5%
U17 = SN74LVC1G08_0: IC - SINGLE 2-INPUT POSITIVE-AND GATE, VCC 1.65-5.0V, DSF PACKAGE; Agile IPN: P01-17851R; Item Num: E67345-001; Lead Free Status: Yes; Manufacturer: Texas Instruments; Num Pins: 6; Part Class: ICs; RoHS Compliant: Yes
C319 C321 C323-C325 C327 C329-C331 C333 C335 = CAP: CAP - CERAMIC, 1PF, +/-0.25PF,  50V, 0402, C0G; AGILE_LINK: http://sj-agile9app/Agile/PLMServlet?action=OpenEmailObject&classid=10000&objid=218192110; Item Num: K13552-001; LIFECYCLE_PHASE: Active; MFR_LIFECYCLE: Active; Manufacturer: Murata; Manufacturer Part Num: GJM1555C1H1R0CB01D; Num Pins: 2; PART_SUBCLASS: CAPACITORS; RATED_VOLTAGE: 50V; RoHS Compliant: RoHS Compliant
J5 = PCIE_Bracket_X16_1: Manufacturer: NA; Manufacturer's Part No.: NA
R147-R149 R153 R156 R157 R999 = RESISTOR: RES 4.7K OHM 1/16W 5% 0402 SMD; Item Num: A93549-020; Lead Free Status: No; Manufacturer: Panasonic; Manufacturer Part Num: ERJ-2GEJ472X; Manufacturer's Part No.: ERJ-2GEJ472X; Num Pins: 2; Part Class: RESISTORS; Price: 0; RoHS Compliant: Yes
R150 R154 R155 = RESISTOR: RES,10.0K OHMS,1.0%,1/16W, 0402; AGILE_LINK: http://sj-agile9app/Agile/PLMServlet?action=OpenEmailObject&classid=10000&objid=146548997; Item Num: K28115-001; LIFECYCLE_PHASE: Active; Lead Free Status: No; MFR_LIFECYCLE: Active; Manufacturer: Panasonic; Manufacturer Part Num: ERJ-2RKF1002X; Num Pins: 2; PART_SUBCLASS: RESISTORS; POWER: 1/16W; RoHS Compliant: Yes; TOLERANCE: +/-1%
R151 R152 = RES_0_OHM_5%_1_16W_0402_SMD: Item Num: H30887-001
R158 = RESISTOR: RES,100K OHMS,1.0%,1/16W,0402; Item Num: A78422-001; Lead Free Status: No; Manufacturer: Panasonic; Manufacturer Part Num: ERJ-2RKF1003X; Num Pins: 2; Part Class: Resistors; Price: 0; RoHS Compliant: Yes
SW1 = SPST4: SWITCHES - 4 POS, 8 PIN, Ultra-mini SMT Half-pitch Slider DIP Switch; Item Num: K15518-001; Lead Free Status: Yes; Manufacturer: C & K Components/ITT Industries; Num Pins: 8; Part Class: Switches; Price: 0; RoHS Compliant: Yes; Supplier: 8
U16 = 24AA024: IC,EEPROM,BL,SOIC,400KHz,N/A,I2C,2KB,N/A; Item Num: K41506-001; Manufacturer: Microchip
C295 C297 C299 C301 C303 = CAP: CAP CER 1UF 25V X6S 0402; Item Num: H81594-003; Lead Free Status: Yes; Manufacturer: Murata; Manufacturer Part Num: GRM155C81E105KE11D; Num Pins: 2; Part Class: CAPACITORS; RATED_VOLTAGE: 25V; RoHS Compliant: Yes; Temperature Coefficient: X6S
C296 C298 C300 C302 C304 = CAP: CAP CER 0.1UF 25V X6S 0402; Dielectric: X6S; Item Num: K19434-001; LIFECYCLE_PHASE: Active; Lead Free Status: Lead Free; Manufacturer: Murata; Manufacturer Part Num: GRM155C81E104KA12D; Num Pins: 2; Part Class: CAPACITORS; RATED_VOLTAGE: 25V; RoHS Compliant: RoHS Compliant; Tolerance: 10%
C305 = CAP: CAP CER 2.2UF 10V X6S 0402; Dielectric: X6S; Item Num: H90637-001; LIFECYCLE_PHASE: Active; Lead Free Status: Lead Free; Manufacturer: Murata; Manufacturer Part Num: GRM155C81A225KE44D; Num Pins: 2; Part Class: CAPACITORS; RATED_VOLTAGE: 10V; RoHS Compliant: RoHS Compliant; Tolerance: 10%
R131-R135 = RESISTOR: RES,4.70K OHMS,1.0%,1/16W,0402; AGILE_LINK: http://sj-agile9app/Agile/PLMServlet?action=OpenEmailObject&classid=10000&objid=146753272; Item Num: D60468-001; LIFECYCLE_PHASE: Active; Lead Free Status: No; MFR_LIFECYCLE: Active; Manufacturer: Vishay; Manufacturer Part Num: CRCW04024K70FKED; Num Pins: 2; PART_SUBCLASS: RESISTORS; POWER: 1/16W; RoHS Compliant: Yes; TOLERANCE: 1%
U14 = FPC202: IC, Dual Port Controller with Expanded I/Os; Item Num: K21999-001; Manufacturer: Texas Instruments

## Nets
GND: C295.1 C296.1 C297.1 C298.1 C299.1 C300.1 C301.1 C302.1 C303.1 C304.1 C305.1 C308.2 C309.2 C310.2 C340.2 C353.1 C370.2 C371.2 C372.2 J5.A4(GND) J5.A12(GND) J5.A15(GND) J5.A18(GND) J5.A20(GND) J5.A23(GND) J5.A24(GND) J5.A27(GND) J5.A28(GND) J5.A31(GND) J5.A34(GND) J5.A37(GND) J5.A38(GND) J5.A41(GND) J5.A42(GND) J5.A45(GND) J5.A46(GND) J5.A49(GND) J5.A51(GND) J5.A54(GND) J5.A55(GND) J5.A58(GND) J5.A59(GND) J5.A62(GND) J5.A63(GND) J5.A66(GND) J5.A67(GND) J5.A70(GND) J5.A71(GND) J5.A74(GND) J5.A75(GND) J5.A78(GND) J5.A79(GND) J5.A82(GND) J5.B4(GND) J5.B7(GND) J5.B13(GND) J5.B16(GND) J5.B18(GND) J5.B21(GND) J5.B22(GND) J5.B25(GND) J5.B26(GND) J5.B29(GND) J5.B32(GND) J5.B35(GND) J5.B36(GND) J5.B39(GND) J5.B40(GND) J5.B43(GND) J5.B44(GND) J5.B47(GND) J5.B49(GND) J5.B52(GND) J5.B53(GND) J5.B56(GND) J5.B57(GND) J5.B60(GND) J5.B61(GND) J5.B64(GND) J5.B65(GND) J5.B68(GND) J5.B69(GND) J5.B72(GND) J5.B73(GND) J5.B76(GND) J5.B77(GND) J5.B80(GND) J6.A1(GND) J6.A4(GND) J6.A7(GND) J6.A10(GND) J6.A13(GND) J6.A16(GND) J6.A19(GND) J6.A22(GND) J6.A25(GND) J6.A28(GND) J6.A31(GND) J6.A34(GND) J6.A37(GND) J6.B1(GND) J6.B4(GND) J6.B7(GND) J6.B10(GND) J6.B13(GND) J6.B16(GND) J6.B19(GND) J6.B22(GND) J6.B25(GND) J6.B28(GND) J6.B31(GND) J6.B34(GND) J6.B37(GND) J6.MH1 J6.MH2 J6.MH3 J6.MH4 J7.A1(GND) J7.A4(GND) J7.A7(GND) J7.A10(GND) J7.A13(GND) J7.A16(GND) J7.A19(GND) J7.A22(GND) J7.A25(GND) J7.A28(GND) J7.A31(GND) J7.A34(GND) J7.A37(GND) J7.B1(GND) J7.B4(GND) J7.B7(GND) J7.B10(GND) J7.B13(GND) J7.B16(GND) J7.B19(GND) J7.B22(GND) J7.B25(GND) J7.B28(GND) J7.B31(GND) J7.B34(GND) J7.B37(GND) J7.MH1 J7.MH2 J7.MH3 J7.MH4 R137.2 R146.2 R159.1 R160.1 R161.1 R162.1 R163.1 R164.1 R165.1 R166.1 R167.1 R168.1 R169.1 R174.1 R175.1 R176.1 R177.1 R178.2 R179.2 R866.1 R867.2 R936.2 R937.2 U6.CD60(GND) U6.DL78(FHTL12A_RX_CH3P) U6.DP79(FHTL12A_RX_CH3N) U6.EC76(REFCLK_FHTL12A_CH1P) U6.EC78(FHTL12A_RX_CH2P) U6.EF79(FHTL12A_RX_CH2N) U6.EK76(REFCLK_FHTL12A_CH1N) U6.ET78(FHTL12A_RX_CH1P) U6.EW75(REFCLK_FHTL12A_CH0P) U6.EW79(FHTL12A_RX_CH1N) U6.FB76(REFCLK_FHTL12A_CH0N) U6.FH78(FHTL12A_RX_CH0P) U6.FL79(FHTL12A_RX_CH0N) U6.JY64(GND) U14.21(CTRL4) U14.27(GND) U14.28(CTRL3) U14.57(DAP_(GND)) U15.7(GND) U16.4(VSS) U17.3(GND) U18.7(GND) ; also on sheet 9 10 11 13 14 15 16 17 18 19 20 21 22 23 25 26 33 34 35 36 38 39 40 41 42 43 44 45 46 47 48 49 50 51 52 53 54 55 56 57 58 59 60 61 62 63 64 65 66 67 68 69 70 71 72 73 74 75 76 77
1p0V_VCCCLK_GXR: C353.2 R183.2 R6324.1 U17.5(VCC) ; also on sheet 33 38 74 76
1p2V_DDR4_CH01: C372.1 U18.1(VL) U18.8(TSn) ; also on sheet 9 10 11 14 15 16 39 46 47 52 70 72 76 77
1p2V_DDR4_CH2: C309.1 R157.1 R999.1 U15.1(VL) U15.8(TSn) ; also on sheet 19 20 39 71 72 76
1p8V_VCCCLK_GXF: R145.2 R856.1 ; also on sheet 38 39
3p3V_STBY: C340.1 R147.2 R148.2 R158.1 R170.2 R171.2 R172.2 R173.2 U16.8(VCC) ; also on sheet 44 48 49 50 51 52 53 57 77
CLK_100M_CXL_CONN_C_N: J6.B12(CLK0_DN) R186.1
CLK_100M_CXL_CONN_C_P: J6.B11(CLK0_DP) R185.1
CLK_CXL_CONN_N: R186.2 ; also on sheet 45
CLK_CXL_CONN_P: R185.2 ; also on sheet 45
CXL_PERST1_N: J6.A29(PERST1_N) R187.2
CXL_PERST2_N: J7.A11(PERST0_N) R188.2
CXL_PERST3_N: J7.A29(PERST1_N) R189.2
CXL_PERSTn: J6.A11(PERST0_N) R187.1 R188.1 R189.1 ; also on sheet 33 48 52
CXL_PRSNTx1_N: J6.A12(PRSNT0_N) U18.13(IOVCC1)
CXL_PRSNTx4_N: J6.A30(PRSNT1_N) U18.12(IOVCC2)
CXL_PRSNTx8_N: J7.A12(PRSNT0_N) U18.11(IOVCC3)
CXL_PRSNTx16_N: J7.A30(PRSNT1_N) U18.10(IOVCC4)
CXL_RX_N0: J6.A3(RX0_0N) ; also on sheet 33
CXL_RX_N1: J6.A6(RX0_1N) ; also on sheet 33
CXL_RX_N2: J6.A15(RX0_2N) ; also on sheet 33
CXL_RX_N3: J6.A18(RX0_3N) ; also on sheet 33
CXL_RX_N4: J6.A21(RX1_0N) ; also on sheet 33
CXL_RX_N5: J6.A24(RX1_1N) ; also on sheet 33
CXL_RX_N6: J6.A33(RX1_2N) ; also on sheet 33
CXL_RX_N7: J6.A36(RX1_3N) ; also on sheet 33
CXL_RX_N8: J7.A3(RX0_0N) ; also on sheet 33
CXL_RX_N9: J7.A6(RX0_1N) ; also on sheet 33
CXL_RX_N10: J7.A15(RX0_2N) ; also on sheet 33
CXL_RX_N11: J7.A18(RX0_3N) ; also on sheet 33
CXL_RX_N12: J7.A21(RX1_0N) ; also on sheet 33
CXL_RX_N13: J7.A24(RX1_1N) ; also on sheet 33
CXL_RX_N14: J7.A33(RX1_2N) ; also on sheet 33
CXL_RX_N15: J7.A36(RX1_3N) ; also on sheet 33
CXL_RX_P0: J6.A2(RX0_0P) ; also on sheet 33
CXL_RX_P1: J6.A5(RX0_1P) ; also on sheet 33
CXL_RX_P2: J6.A14(RX0_2P) ; also on sheet 33
CXL_RX_P3: J6.A17(RX0_3P) ; also on sheet 33
CXL_RX_P4: J6.A20(RX1_0P) ; also on sheet 33
CXL_RX_P5: J6.A23(RX1_1P) ; also on sheet 33
CXL_RX_P6: J6.A32(RX1_2P) ; also on sheet 33
CXL_RX_P7: J6.A35(RX1_3P) ; also on sheet 33
CXL_RX_P8: J7.A2(RX0_0P) ; also on sheet 33
CXL_RX_P9: J7.A5(RX0_1P) ; also on sheet 33
CXL_RX_P10: J7.A14(RX0_2P) ; also on sheet 33
CXL_RX_P11: J7.A17(RX0_3P) ; also on sheet 33
CXL_RX_P12: J7.A20(RX1_0P) ; also on sheet 33
CXL_RX_P13: J7.A23(RX1_1P) ; also on sheet 33
CXL_RX_P14: J7.A32(RX1_2P) ; also on sheet 33
CXL_RX_P15: J7.A35(RX1_3P) ; also on sheet 33
CXL_SMB_ALERT_N: J6.B9(SMB0_ALERT_N) ; also on sheet 48
CXL_TX_C_N0: C355.2 J6.B3(TX0_0N)
CXL_TX_C_N1: C357.2 J6.B6(TX0_1N)
CXL_TX_C_N2: C359.2 J6.B15(TX0_2N)
CXL_TX_C_N3: C361.2 J6.B18(TX0_3N)
CXL_TX_C_N4: C363.2 J6.B21(TX1_0N)
CXL_TX_C_N5: C365.2 J6.B24(TX1_1N)
CXL_TX_C_N6: C367.2 J6.B33(TX1_2N)
CXL_TX_C_N7: C369.2 J6.B36(TX1_3N)
CXL_TX_C_N8: C374.2 J7.B3(TX0_0N)
CXL_TX_C_N9: C376.2 J7.B6(TX0_1N)
CXL_TX_C_N10: C378.2 J7.B15(TX0_2N)
CXL_TX_C_N11: C380.2 J7.B18(TX0_3N)
CXL_TX_C_N12: C382.2 J7.B21(TX1_0N)
CXL_TX_C_N13: C384.2 J7.B24(TX1_1N)
CXL_TX_C_N14: C386.2 J7.B33(TX1_2N)
CXL_TX_C_N15: C388.2 J7.B36(TX1_3N)
CXL_TX_C_P0: C354.2 J6.B2(TX0_0P)
CXL_TX_C_P1: C356.2 J6.B5(TX0_1P)
CXL_TX_C_P2: C358.2 J6.B14(TX0_2P)
CXL_TX_C_P3: C360.2 J6.B17(TX0_3P)
CXL_TX_C_P4: C362.2 J6.B20(TX1_0P)
CXL_TX_C_P5: C364.2 J6.B23(TX1_1P)
CXL_TX_C_P6: C366.2 J6.B32(TX1_2P)
CXL_TX_C_P7: C368.2 J6.B35(TX1_3P)
CXL_TX_C_P8: C373.2 J7.B2(TX0_0P)
CXL_TX_C_P9: C375.2 J7.B5(TX0_1P)
CXL_TX_C_P10: C377.2 J7.B14(TX0_2P)
CXL_TX_C_P11: C379.2 J7.B17(TX0_3P)
CXL_TX_C_P12: C381.2 J7.B20(TX1_0P)
CXL_TX_C_P13: C383.2 J7.B23(TX1_1P)
CXL_TX_C_P14: C385.2 J7.B32(TX1_2P)
CXL_TX_C_P15: C387.2 J7.B35(TX1_3P)
CXL_TX_N0: C355.1 ; also on sheet 33
CXL_TX_N1: C357.1 ; also on sheet 33
CXL_TX_N2: C359.1 ; also on sheet 33
CXL_TX_N3: C361.1 ; also on sheet 33
CXL_TX_N4: C363.1 ; also on sheet 33
CXL_TX_N5: C365.1 ; also on sheet 33
CXL_TX_N6: C367.1 ; also on sheet 33
CXL_TX_N7: C369.1 ; also on sheet 33
CXL_TX_N8: C374.1 ; also on sheet 33
CXL_TX_N9: C376.1 ; also on sheet 33
CXL_TX_N10: C378.1 ; also on sheet 33
CXL_TX_N11: C380.1 ; also on sheet 33
CXL_TX_N12: C382.1 ; also on sheet 33
CXL_TX_N13: C384.1 ; also on sheet 33
CXL_TX_N14: C386.1 ; also on sheet 33
CXL_TX_N15: C388.1 ; also on sheet 33
CXL_TX_P0: C354.1 ; also on sheet 33
CXL_TX_P1: C356.1 ; also on sheet 33
CXL_TX_P2: C358.1 ; also on sheet 33
CXL_TX_P3: C360.1 ; also on sheet 33
CXL_TX_P4: C362.1 ; also on sheet 33
CXL_TX_P5: C364.1 ; also on sheet 33
CXL_TX_P6: C366.1 ; also on sheet 33
CXL_TX_P7: C368.1 ; also on sheet 33
CXL_TX_P8: C373.1 ; also on sheet 33
CXL_TX_P9: C375.1 ; also on sheet 33
CXL_TX_P10: C377.1 ; also on sheet 33
CXL_TX_P11: C379.1 ; also on sheet 33
CXL_TX_P12: C381.1 ; also on sheet 33
CXL_TX_P13: C383.1 ; also on sheet 33
CXL_TX_P14: C385.1 ; also on sheet 33
CXL_TX_P15: C387.1 ; also on sheet 33
DFX_1_TOG: R865.2 ; also on sheet 50
FM41_14C_PCIE_PERSTN: R6297.1 R6324.2 ; also on sheet 41
FM41_15C_CXL_PERSTN: U6.HV34(NC8) ; also on sheet 33
FPGA_CXL_PRSNTx1_N: U18.2(IOVL1) ; also on sheet 17
FPGA_CXL_PRSNTx4_N: U18.3(IOVL2) ; also on sheet 17
FPGA_CXL_PRSNTx8_N: U18.4(IOVL3) ; also on sheet 17
FPGA_CXL_PRSNTx16_N: U18.5(IOVL4) ; also on sheet 17
FPGA_PCIE_PERSTN: R183.1 R184.2 U6.CD58(I_PIN_PERST_N_14C_GXR)
FPGA_TEMP0Cn: U6.CG55(TEMPDIODE0CN) ; also on sheet 52
FPGA_TEMP0Cp: U6.CN55(TEMPDIODE0CP) ; also on sheet 52
FPGA_TEMP1n: U6.HM60(TEMPDIODE1N) ; also on sheet 52
FPGA_TEMP1p: U6.HJ59(TEMPDIODE1P) ; also on sheet 52
FPGA_TEMP3n: U6.BV66(TEMPDIODE3N) ; also on sheet 52
FPGA_TEMP3p: U6.BR68(TEMPDIODE3P) ; also on sheet 52
GXF_PERSTn: R856.2 U6.JL61(I_PIN_PERST_N_12A_GXF) ; also on sheet 48
I2C2_SCL: J6.A8(SMB0_SCL) U14.23(CTRL1) ; also on sheet 46 48 50 52
I2C2_SDA: J6.A9(SMB0_SDA) U14.24(CTRL2) ; also on sheet 46 48 50 52
IO_3p3V: C295.2 C296.2 C297.2 C298.2 C299.2 C300.2 C301.2 C302.2 C303.2 C304.2 C308.1 C310.1 C370.1 C371.1 R131.2 R132.2 R133.2 R134.2 R135.2 R136.1 R149.2 R150.1 R153.2 R154.2 R156.1 R1001.2 U14.9(VDD1_1) U14.20(VDD2_1) U14.26(VDD2_2) U14.43(VDD1_2) U14.54(VDD1_3) U15.14(VCC) U18.14(VCC) ; also on sheet 25 26 43 44 46 47 48 52 73
PCIE_1V2_CLKREQn: R157.2 U15.5(IOVL4) ; also on sheet 24
PCIE_CLKREQn: C319.1 J5.B12(RSVD1) R156.2 U15.10(IOVCC4)
PCIE_EP_3p3V: J5.A9(+3_3V) J5.A10(+3_3V) J5.B8(+3_3V)
PCIE_EP_3V3_WAKEN: R152.2 R155.2 U15.11(IOVCC3)
PCIE_EP_12V: J5.A2(+12V) J5.A3(+12V) J5.B1(+12V) J5.B2(+12V) J5.B3(+12V) ; also on sheet 53
PCIE_EP_JTAG_TCK: J5.A5(JTAG_TCK) ; also on sheet 52
PCIE_EP_JTAG_TDI: J5.A6(JTAG_TDI) R149.1 ; also on sheet 52
PCIE_EP_JTAG_TDO: J5.A7(JTAG_TDO) ; also on sheet 52
PCIE_EP_JTAG_TMS: J5.A8(JTAG_TMS) R153.1 ; also on sheet 52
PCIE_EP_PERSTN: J5.A11(PERST_N) R154.1 R1000.1 ; also on sheet 48
PCIE_EP_PRSNT_N: J5.A1(PRSNT1_N) SW1.1(A1) SW1.2(A2) SW1.3(A3) SW1.4(A4)
PCIE_EP_PRSNT_Nx1: C330.1 J5.B17(PRSNT2n_X1) SW1.5(B4)
PCIE_EP_PRSNT_Nx4: C331.1 J5.B31(PRSNT2n_X4) SW1.6(B3)
PCIE_EP_PRSNT_Nx8: C333.1 J5.B48(PRSNT2n_X8) SW1.7(B2)
PCIE_EP_PRSNT_Nx16: C335.1 J5.B81(PRSNT2n_X16) SW1.8(B1)
PCIE_EP_RX_CN0: C307.2 J5.A17(PER0N)
PCIE_EP_RX_CN1: C312.2 J5.A22(PER1N)
PCIE_EP_RX_CN2: C314.2 J5.A26(PER2N)
PCIE_EP_RX_CN3: C316.2 J5.A30(PER3N)
PCIE_EP_RX_CN4: C318.2 J5.A36(PER4N)
PCIE_EP_RX_CN5: C322.2 J5.A40(PER5N)
PCIE_EP_RX_CN6: C328.2 J5.A44(PER6N)
PCIE_EP_RX_CN7: C334.2 J5.A48(PER7N)
PCIE_EP_RX_CN8: C337.2 J5.A53(PER8N)
PCIE_EP_RX_CN9: C339.2 J5.A57(PER9N)
PCIE_EP_RX_CN10: C342.2 J5.A61(PER10N)
PCIE_EP_RX_CN11: C344.2 J5.A65(PER11N)
PCIE_EP_RX_CN12: C346.2 J5.A69(PER12N)
PCIE_EP_RX_CN13: C348.2 J5.A73(PER13N)
PCIE_EP_RX_CN14: C350.2 J5.A77(PER14N)
PCIE_EP_RX_CN15: C352.2 J5.A81(PER15N)
PCIE_EP_RX_CP0: C306.2 J5.A16(PER0P)
PCIE_EP_RX_CP1: C311.2 J5.A21(PER1P)
PCIE_EP_RX_CP2: C313.2 J5.A25(PER2P)
PCIE_EP_RX_CP3: C315.2 J5.A29(PER3P)
PCIE_EP_RX_CP4: C317.2 J5.A35(PER4P)
PCIE_EP_RX_CP5: C320.2 J5.A39(PER5P)
PCIE_EP_RX_CP6: C326.2 J5.A43(PER6P)
PCIE_EP_RX_CP7: C332.2 J5.A47(PER7P)
PCIE_EP_RX_CP8: C336.2 J5.A52(PER8P)
PCIE_EP_RX_CP9: C338.2 J5.A56(PER9P)
PCIE_EP_RX_CP10: C341.2 J5.A60(PER10P)
PCIE_EP_RX_CP11: C343.2 J5.A64(PER11P)
PCIE_EP_RX_CP12: C345.2 J5.A68(PER12P)
PCIE_EP_RX_CP13: C347.2 J5.A72(PER13P)
PCIE_EP_RX_CP14: C349.2 J5.A76(PER14P)
PCIE_EP_RX_CP15: C351.2 J5.A80(PER15P)
PCIE_EP_RX_N0: C307.1 U6.DH73(GXRL14C_TX_CH0N)
PCIE_EP_RX_N1: C312.1 U6.DE76(GXRL14C_TX_CH1N)
PCIE_EP_RX_N2: C314.1 U6.CT73(GXRL14C_TX_CH2N)
PCIE_EP_RX_N3: C316.1 U6.CM76(GXRL14C_TX_CH3N)
PCIE_EP_RX_N4: C318.1 U6.CC73(GXRL14C_TX_CH4N)
PCIE_EP_RX_N5: C322.1 U6.BY76(GXRL14C_TX_CH5N)
PCIE_EP_RX_N6: C328.1 U6.BL73(GXRL14C_TX_CH6N)
PCIE_EP_RX_N7: C334.1 U6.BH76(GXRL14C_TX_CH7N)
PCIE_EP_RX_N8: C337.1 U6.AW73(GXRL14C_TX_CH8N)
PCIE_EP_RX_N9: C339.1 U6.AR76(GXRL14C_TX_CH9N)
PCIE_EP_RX_N10: C342.1 U6.AF73(GXRL14C_TX_CH10N)
PCIE_EP_RX_N11: C344.1 U6.AC76(GXRL14C_TX_CH11N)
PCIE_EP_RX_N12: C346.1 U6.T73(GXRL14C_TX_CH12N)
PCIE_EP_RX_N13: C348.1 U6.G73(GXRL14C_TX_CH13N)
PCIE_EP_RX_N14: C350.1 U6.E69(GXRL14C_TX_CH14N)
PCIE_EP_RX_N15: C352.1 U6.P69(GXRL14C_TX_CH15N)
PCIE_EP_RX_P0: C306.1 U6.DL74(GXRL14C_TX_CH0P)
PCIE_EP_RX_P1: C311.1 U6.DB77(GXRL14C_TX_CH1P)
PCIE_EP_RX_P2: C313.1 U6.CW74(GXRL14C_TX_CH2P)
PCIE_EP_RX_P3: C315.1 U6.CJ77(GXRL14C_TX_CH3P)
PCIE_EP_RX_P4: C317.1 U6.CF74(GXRL14C_TX_CH4P)
PCIE_EP_RX_P5: C320.1 U6.BU77(GXRL14C_TX_CH5P)
PCIE_EP_RX_P6: C326.1 U6.BP74(GXRL14C_TX_CH6P)
PCIE_EP_RX_P7: C332.1 U6.BE77(GXRL14C_TX_CH7P)
PCIE_EP_RX_P8: C336.1 U6.BB74(GXRL14C_TX_CH8P)
PCIE_EP_RX_P9: C338.1 U6.AM77(GXRL14C_TX_CH9P)
PCIE_EP_RX_P10: C341.1 U6.AJ74(GXRL14C_TX_CH10P)
PCIE_EP_RX_P11: C343.1 U6.Y77(GXRL14C_TX_CH11P)
PCIE_EP_RX_P12: C345.1 U6.V74(GXRL14C_TX_CH12P)
PCIE_EP_RX_P13: C347.1 U6.K74(GXRL14C_TX_CH13P)
PCIE_EP_RX_P14: C349.1 U6.C71(GXRL14C_TX_CH14P)
PCIE_EP_RX_P15: C351.1 U6.M71(GXRL14C_TX_CH15P)
PCIE_EP_SMBCLK: J5.B5(SMCLK) R147.1 U16.6(SCL) ; also on sheet 50
PCIE_EP_SMBDAT: J5.B6(SMDAT) R148.1 U16.5(SDA) ; also on sheet 50
PCIE_EP_TX_N0: J5.B15(PET0N) U6.DB83(GXRL14C_RX_CH0N)
PCIE_EP_TX_N1: J5.B20(PET1N) U6.CT79(GXRL14C_RX_CH1N)
PCIE_EP_TX_N2: J5.B24(PET2N) U6.CJ83(GXRL14C_RX_CH2N)
PCIE_EP_TX_N3: J5.B28(PET3N) U6.CC79(GXRL14C_RX_CH3N)
PCIE_EP_TX_N4: J5.B34(PET4N) U6.BU83(GXRL14C_RX_CH4N)
PCIE_EP_TX_N5: J5.B38(PET5N) U6.BL79(GXRL14C_RX_CH5N)
PCIE_EP_TX_N6: J5.B42(PET6N) U6.BE83(GXRL14C_RX_CH6N)
PCIE_EP_TX_N7: J5.B46(PET7N) U6.AW79(GXRL14C_RX_CH7N)
PCIE_EP_TX_N8: J5.B51(PET8N) U6.AM83(GXRL14C_RX_CH8N)
PCIE_EP_TX_N9: J5.B55(PET9N) U6.AF79(GXRL14C_RX_CH9N)
PCIE_EP_TX_N10: J5.B59(PET10N) U6.Y83(GXRL14C_RX_CH10N)
PCIE_EP_TX_N11: J5.B63(PET11N) U6.T79(GXRL14C_RX_CH11N)
PCIE_EP_TX_N12: J5.B67(PET12N) U6.M83(GXRL14C_RX_CH12N)
PCIE_EP_TX_N13: J5.B71(PET13N) U6.G79(GXRL14C_RX_CH13N)
PCIE_EP_TX_N14: J5.B75(PET14N) U6.P76(GXRL14C_RX_CH14N)
PCIE_EP_TX_N15: J5.B79(PET15N) U6.E76(GXRL14C_RX_CH15N)
PCIE_EP_TX_P0: J5.B14(PET0P) U6.DE82(GXRL14C_RX_CH0P)
PCIE_EP_TX_P1: J5.B19(PET1P) U6.CW80(GXRL14C_RX_CH1P)
PCIE_EP_TX_P2: J5.B23(PET2P) U6.CM82(GXRL14C_RX_CH2P)
PCIE_EP_TX_P3: J5.B27(PET3P) U6.CF80(GXRL14C_RX_CH3P)
PCIE_EP_TX_P4: J5.B33(PET4P) U6.BY82(GXRL14C_RX_CH4P)
PCIE_EP_TX_P5: J5.B37(PET5P) U6.BP80(GXRL14C_RX_CH5P)
PCIE_EP_TX_P6: J5.B41(PET6P) U6.BH82(GXRL14C_RX_CH6P)
PCIE_EP_TX_P7: J5.B45(PET7P) U6.BB80(GXRL14C_RX_CH7P)
PCIE_EP_TX_P8: J5.B50(PET8P) U6.AR82(GXRL14C_RX_CH8P)
PCIE_EP_TX_P9: J5.B54(PET9P) U6.AJ80(GXRL14C_RX_CH9P)
PCIE_EP_TX_P10: J5.B58(PET10P) U6.AC82(GXRL14C_RX_CH10P)
PCIE_EP_TX_P11: J5.B62(PET11P) U6.V80(GXRL14C_RX_CH11P)
PCIE_EP_TX_P12: J5.B66(PET12P) U6.P82(GXRL14C_RX_CH12P)
PCIE_EP_TX_P13: J5.B70(PET13P) U6.K80(GXRL14C_RX_CH13P)
PCIE_EP_TX_P14: J5.B74(PET14P) U6.M77(GXRL14C_RX_CH14P)
PCIE_EP_TX_P15: J5.B78(PET15P) U6.C77(GXRL14C_RX_CH15P)
PCIE_EP_WAKEN: R999.2 U15.4(IOVL3) ; also on sheet 24
PCIE_PERSTn: U17.2(B) ; also on sheet 48
PCIE_PWRBRKN: C323.1 J5.B30(RSVD3) R158.2 ; also on sheet 48
PCIE_RSV2: C321.1 J5.A19(RSVD2)
PCIE_RSV4: C324.1 J5.A32(RSVD4)
PCIE_RSV5: C325.1 J5.A33(RSVD5)
PCIE_RSV6: C327.1 J5.B82(RSVD6)
PCIE_RSV7: C329.1 J5.A50(RSVD7)
QSFPDD0_3V3_INT_L: U14.41(P0_S0_IN_A) ; also on sheet 25
QSFPDD0_3V3_LPMODE: U14.38(P0_S0_OUT_B) ; also on sheet 25
QSFPDD0_3V3_MODPRS_L: U14.39(P0_S0_IN_B) ; also on sheet 25
QSFPDD0_3V3_RESET_L: U14.40(P0_S0_OUT_A) ; also on sheet 25
QSFPDD0_I2C_SCL: R133.1 U14.36(P0_MOD_SCL) ; also on sheet 25
QSFPDD0_I2C_SDA: R132.1 U14.35(P0_MOD_SDA) ; also on sheet 25
QSFPDD0_RX0_N: U6.ME76(FGTL12A_RX_Q0_CH0N) ; also on sheet 25
QSFPDD0_RX0_P: U6.MB77(FGTL12A_RX_Q0_CH0P) ; also on sheet 25
QSFPDD0_RX1_N: U6.LT76(FGTL12A_RX_Q0_CH1N) ; also on sheet 25
QSFPDD0_RX1_P: U6.LP77(FGTL12A_RX_Q0_CH1P) ; also on sheet 25
QSFPDD0_RX2_N: U6.LV79(FGTL12A_RX_Q0_CH2N) ; also on sheet 25
QSFPDD0_RX2_P: U6.LY80(FGTL12A_RX_Q0_CH2P) ; also on sheet 25
QSFPDD0_RX3_N: U6.LT82(FGTL12A_RX_Q0_CH3N) ; also on sheet 25
QSFPDD0_RX3_P: U6.LP83(FGTL12A_RX_Q0_CH3P) ; also on sheet 25
QSFPDD0_RX4_N: U6.LK79(FGTL12A_RX_Q1_CH0N) ; also on sheet 25
QSFPDD0_RX4_P: U6.LM80(FGTL12A_RX_Q1_CH0P) ; also on sheet 25
QSFPDD0_RX5_N: U6.LG82(FGTL12A_RX_Q1_CH1N) ; also on sheet 25
QSFPDD0_RX5_P: U6.LD83(FGTL12A_RX_Q1_CH1P) ; also on sheet 25
QSFPDD0_RX6_N: U6.KV79(FGTL12A_RX_Q1_CH2N) ; also on sheet 25
QSFPDD0_RX6_P: U6.LA80(FGTL12A_RX_Q1_CH2P) ; also on sheet 25
QSFPDD0_RX7_N: U6.KP82(FGTL12A_RX_Q1_CH3N) ; also on sheet 25
QSFPDD0_RX7_P: U6.KL83(FGTL12A_RX_Q1_CH3P) ; also on sheet 25
QSFPDD0_TX0_N: U6.ME69(FGTL12A_TX_Q0_CH0N) ; also on sheet 25
QSFPDD0_TX0_P: U6.MB71(FGTL12A_TX_Q0_CH0P) ; also on sheet 25
QSFPDD0_TX1_N: U6.MG73(FGTL12A_TX_Q0_CH1N) ; also on sheet 25
QSFPDD0_TX1_P: U6.MJ74(FGTL12A_TX_Q0_CH1P) ; also on sheet 25
QSFPDD0_TX2_N: U6.LV73(FGTL12A_TX_Q0_CH2N) ; also on sheet 25
QSFPDD0_TX2_P: U6.LY74(FGTL12A_TX_Q0_CH2P) ; also on sheet 25
QSFPDD0_TX3_N: U6.LK73(FGTL12A_TX_Q0_CH3N) ; also on sheet 25
QSFPDD0_TX3_P: U6.LM74(FGTL12A_TX_Q0_CH3P) ; also on sheet 25
QSFPDD0_TX4_N: U6.LG76(FGTL12A_TX_Q1_CH0N) ; also on sheet 25
QSFPDD0_TX4_P: U6.LD77(FGTL12A_TX_Q1_CH0P) ; also on sheet 25
QSFPDD0_TX5_N: U6.KV73(FGTL12A_TX_Q1_CH1N) ; also on sheet 25
QSFPDD0_TX5_P: U6.LA74(FGTL12A_TX_Q1_CH1P) ; also on sheet 25
QSFPDD0_TX6_N: U6.KP76(FGTL12A_TX_Q1_CH2N) ; also on sheet 25
QSFPDD0_TX6_P: U6.KL77(FGTL12A_TX_Q1_CH2P) ; also on sheet 25
QSFPDD0_TX7_N: U6.KE73(FGTL12A_TX_Q1_CH3N) ; also on sheet 25
QSFPDD0_TX7_P: U6.KH74(FGTL12A_TX_Q1_CH3P) ; also on sheet 25
QSFPDD1_3V3_INT_L: U14.55(P1_S0_IN_A) ; also on sheet 26
QSFPDD1_3V3_LPMODE: U14.2(P1_S0_OUT_B) ; also on sheet 26
QSFPDD1_3V3_MODPRS_L: U14.1(P1_S0_IN_B) ; also on sheet 26
QSFPDD1_3V3_RESET_L: U14.56(P1_S0_OUT_A) ; also on sheet 26
QSFPDD1_I2C_SCL: R135.1 U14.4(P1_MOD_SCL) ; also on sheet 26
QSFPDD1_I2C_SDA: R134.1 U14.5(P1_MOD_SDA) ; also on sheet 26
QSFPDD1_RX0_N: U6.KE79(FGTL12A_RX_Q2_CH0N) ; also on sheet 26
QSFPDD1_RX0_P: U6.KH80(FGTL12A_RX_Q2_CH0P) ; also on sheet 26
QSFPDD1_RX1_N: U6.KB82(FGTL12A_RX_Q2_CH1N) ; also on sheet 26
QSFPDD1_RX1_P: U6.JW83(FGTL12A_RX_Q2_CH1P) ; also on sheet 26
QSFPDD1_RX2_N: U6.JN79(FGTL12A_RX_Q2_CH2N) ; also on sheet 26
QSFPDD1_RX2_P: U6.JT80(FGTL12A_RX_Q2_CH2P) ; also on sheet 26
QSFPDD1_RX3_N: U6.JK82(FGTL12A_RX_Q2_CH3N) ; also on sheet 26
QSFPDD1_RX3_P: U6.JG83(FGTL12A_RX_Q2_CH3P) ; also on sheet 26
QSFPDD1_RX4_N: U6.JA79(FGTL12A_RX_Q3_CH0N) ; also on sheet 26
QSFPDD1_RX4_P: U6.JD80(FGTL12A_RX_Q3_CH0P) ; also on sheet 26
QSFPDD1_RX5_N: U6.HU82(FGTL12A_RX_Q3_CH1N) ; also on sheet 26
QSFPDD1_RX5_P: U6.HP83(FGTL12A_RX_Q3_CH1P) ; also on sheet 26
QSFPDD1_RX6_N: U6.HE82(FGTL12A_RX_Q3_CH2N) ; also on sheet 26
QSFPDD1_RX6_P: U6.HB83(FGTL12A_RX_Q3_CH2P) ; also on sheet 26
QSFPDD1_RX7_N: U6.GN82(FGTL12A_RX_Q3_CH3N) ; also on sheet 26
QSFPDD1_RX7_P: U6.GK83(FGTL12A_RX_Q3_CH3P) ; also on sheet 26
QSFPDD1_TX0_N: U6.KB76(FGTL12A_TX_Q2_CH0N) ; also on sheet 26
QSFPDD1_TX0_P: U6.JW77(FGTL12A_TX_Q2_CH0P) ; also on sheet 26
QSFPDD1_TX1_N: U6.JN73(FGTL12A_TX_Q2_CH1N) ; also on sheet 26
QSFPDD1_TX1_P: U6.JT74(FGTL12A_TX_Q2_CH1P) ; also on sheet 26
QSFPDD1_TX2_N: U6.JK76(FGTL12A_TX_Q2_CH2N) ; also on sheet 26
QSFPDD1_TX2_P: U6.JG77(FGTL12A_TX_Q2_CH2P) ; also on sheet 26
QSFPDD1_TX3_N: U6.HU76(FGTL12A_TX_Q2_CH3N) ; also on sheet 26
QSFPDD1_TX3_P: U6.HP77(FGTL12A_TX_Q2_CH3P) ; also on sheet 26
QSFPDD1_TX4_N: U6.HH79(FGTL12A_TX_Q3_CH0N) ; also on sheet 26
QSFPDD1_TX4_P: U6.HL80(FGTL12A_TX_Q3_CH0P) ; also on sheet 26
QSFPDD1_TX5_N: U6.HE76(FGTL12A_TX_Q3_CH1N) ; also on sheet 26
QSFPDD1_TX5_P: U6.HB77(FGTL12A_TX_Q3_CH1P) ; also on sheet 26
QSFPDD1_TX6_N: U6.GT79(FGTL12A_TX_Q3_CH2N) ; also on sheet 26
QSFPDD1_TX6_P: U6.GW80(FGTL12A_TX_Q3_CH2P) ; also on sheet 26
QSFPDD1_TX7_N: U6.GK77(FGTL12A_TX_Q3_CH3N) ; also on sheet 26
QSFPDD1_TX7_P: U6.GG78(FGTL12A_TX_Q3_CH3P) ; also on sheet 26
QSFPDD_3V3_PORT_EN: R136.2 R137.1 U14.22(EN) ; also on sheet 47
QSFPDD_3V3_PORT_INT_N: R131.1 U14.25(HOST_INT_N) ; also on sheet 47
REFCLK_CXL_RP_N0: J7.B30(CLK1_DN) ; also on sheet 44
REFCLK_CXL_RP_N1: J7.B12(CLK0_DN) ; also on sheet 44
REFCLK_CXL_RP_P0: J7.B29(CLK1_DP) ; also on sheet 44
REFCLK_CXL_RP_P1: J7.B11(CLK0_DP) ; also on sheet 44
REFCLK_FGT12ACH0_N: R140.2 U6.JP70(REFCLK_FGTL12A_Q0_RX_CH0N) ; also on sheet 43
REFCLK_FGT12ACH0_P: R140.1 U6.JH70(REFCLK_FGTL12A_Q0_RX_CH0P) ; also on sheet 43
REFCLK_FGT12ACH3_N: R142.2 U6.HM70(REFCLK_FGTL12A_Q1_RX_CH3N) ; also on sheet 43
REFCLK_FGT12ACH3_P: R142.1 U6.HJ68(REFCLK_FGTL12A_Q1_RX_CH3P) ; also on sheet 43
REFCLK_FGT12ACH4_N: R143.2 U6.JA73(REFCLK_FGTL12A_Q2_RX_CH4N) ; also on sheet 43
REFCLK_FGT12ACH4_P: R143.1 U6.JD74(REFCLK_FGTL12A_Q2_RX_CH4P) ; also on sheet 43
REFCLK_FGT12ACH5_N: R138.2 U6.HH73(REFCLK_FGTL12A_Q2_RX_CH5N) ; also on sheet 43
REFCLK_FGT12ACH5_P: R138.1 U6.HL74(REFCLK_FGTL12A_Q2_RX_CH5P) ; also on sheet 43
REFCLK_FGT12ACH6_N: R144.2 U6.FU73(REFCLK_FGTL12A_Q3_RX_CH6N) ; also on sheet 43
REFCLK_FGT12ACH6_P: R144.1 U6.FP74(REFCLK_FGTL12A_Q3_RX_CH6P) ; also on sheet 43
REFCLK_FM41_15C_CXL_N: U6.JB26(NC7) ; also on sheet 45
REFCLK_PCIE_14C_CH0_N: R178.1 U6.DM70(REFCLK_GXRL14C_CH0N) ; also on sheet 44
REFCLK_PCIE_14C_CH0_P: R936.1 U6.DR68(REFCLK_GXRL14C_CH0P) ; also on sheet 44
REFCLK_PCIE_14C_CH1_N: R179.1 U6.CR70(REFCLK_GXRL14C_CH1N) ; also on sheet 44
REFCLK_PCIE_14C_CH1_P: R937.1 U6.CU68(REFCLK_GXRL14C_CH1P) ; also on sheet 44
REFCLK_PCIE_EP_EDGE_N: J5.A14(REFCLK-) ; also on sheet 44
REFCLK_PCIE_EP_EDGE_P: J5.A13(REFCLK+) ; also on sheet 44
N31250983: J5.B11(WAKE_N) R152.1
N31253147: R151.2 R155.1
N31253181: J5.B9(JTAG_TRSTN) R150.2
N31257069: J5.B10(+3_3VAUX) R151.1
N37651435: C319.2 R159.2
N37651438: C321.2 R160.2
N37651441: C323.2 R161.2
N37651444: C324.2 R162.2
N37651447: C325.2 R163.2
N37651450: C327.2 R164.2
N37651453: C329.2 R165.2
N37651456: C330.2 R166.2
N37651459: C331.2 R167.2
N37651462: C333.2 R168.2
N37651465: C335.2 R169.2
N40226134: R141.1 U6.HP73(12A_GXF_RCOMP_N_Q2_CH1_FGT)
N40226137: R141.2 U6.HU74(12A_GXF_RCOMP_P_Q2_CH1_FGT)
N40226161: R139.1 U6.EK74(12A_GXF_RCOMP_N_FHT)
N40226164: R139.2 U6.EF73(12A_GXF_RCOMP_P_FHT)
N40297214: R182.1 U6.EA68(14C_GXR_IO_RCOMP_P_0)
N40297218: R182.2 U6.DV70(14C_GXR_IO_RCOMP_N_0)
N40423539: R184.1 R6297.2 U17.4(Y)
N40558736: R171.1 R175.2 U16.3(A2)
N40558738: R172.1 R176.2 U16.2(A1)
N40558740: R170.1 R177.2 U16.1(A0)
N40558777: R173.1 R174.2 U16.7(WP)
N40562266: C305.2 U14.32(CAPL)
N40632752: R145.1 R146.1 U6.JH62(DNU20)
N42980348: R865.1 R866.2 U6.JU61(GND)
N42980629: R867.1 U6.HR63(DNU18)
N45349000: R1000.2 R1001.1 U17.1(A)

Not connected (* = marked no-connect by the designer): J6 A26(SMB1_SCL) A27(SMB1_SDA) B8(NC)* B26(NC)* B27(SMB1_ALERT_N) B29(CLK1_DP) B30(CLK1_DN); J7 A8(SMB0_SCL) A9(SMB0_SDA) A26(SMB1_SCL) A27(SMB1_SDA) B8(NC)* B9(SMB0_ALERT_N) B26(NC)* B27(SMB1_ALERT_N); U6 BR63(DNU54)* BR65(DNU55)* BV64(DNU52)* BV70(DNU53)* CA35(DNU88)* CD30(DNU81)* CD32(DNU101)* CD34(DNU87)* CD56(DNU49)* CD70(DNU50)* CG29(DNU96)* CG31(DNU98)* CG35(DNU82)* CG57(DNU48)* CG59(DNU45)* CG68(DNU51)* CK56(DNU8)* CN31(DNU99)* CN33(DNU85)* CN35(DNU92)* CN57(DNU12)* CR26(DNU95)* CR30(DNU97)* CR32(DNU84)* CR34(DNU90)* CR36(DNU10)* CU31(DNU80)* CU33(DNU83)* CU35(DNU91)* CY32(DNU79)* CY34(DNU86)* CY36(DNU14)* DC31(DNU94)* DC35(DNU100)* DF26(DNU93)* DF70(DNU46)* DJ27(DNU78)* DJ68(DNU47)* DM26(DNU89)* DU82(FHTL12A_TX_CH3P)* DY73(VCC_SENSE_FHT_12A_GXF)* DY81(FHTL12A_TX_CH3N)* EC74(VSS_SENSE_FHT_12A_GXF)* EK72(APROBE2_GXF_FHT12A)* EK82(FHTL12A_TX_CH2P)* EN73(APROBE1_GXF_FHT12A)* EN81(FHTL12A_TX_CH2N)* FB82(FHTL12A_TX_CH1P)* FE73(REFCLK_FGTL12A_Q3_CH9P)* FE81(FHTL12A_TX_CH1N)* FL73(REFCLK_FGTL12A_Q3_CH9N)* FM70(REFCLK_FGTL12A_Q3_RX_CH7N)* FP72(APROBE2_GXF_FGT12A_Q3_CH3)* FP82(FHTL12A_TX_CH0P)* FU81(FHTL12A_TX_CH0N)* FV70(REFCLK_FGTL12A_Q3_RX_CH7P)* FY72(APROBE_GXF_FGT12A_Q3_CH3)* GP70(REFCLK_FGTL12A_Q2_CH8N)* GY70(REFCLK_FGTL12A_Q2_CH8P)* HC59(NC10)* HC68(APROBE_GXF_FGT12A_Q0_CH3)* HF58(DNU44)* HF70(APROBE_GXF_FGT12A_Q2_CH3)* HJ61(DNU24)* HJ63(DNU19)* HJ65(DNU34)* HM58(DNU11)* HM64(DNU15)* HR57(DNU7)* HR61(DNU37)* HR65(DNU35)* HR68(REFCLK_FGTL12A_Q1_RX_CH2N)* HV32(NC9)* HV60(DNU23)* HV62(DNU38)* HV64(DNU30)* HY35(DNU9)* HY61(DNU43)* HY68(REFCLK_FGTL12A_Q1_RX_CH2P)* JB62(DNU42)* JB64(DNU29)* JB70(REFCLK_FGTL12A_Q0_RX_CH1P)* JE35(DNU13)* JE63(DNU41)* JE65(DNU21)* JE68(REFCLK_FGTL12A_Q0_RX_CH1N)* JH60(12A_GXF_IO_PLL_REFCLK)* JH64(DNU22)* JL63(DNU33)* JL65(DNU39)* JP66(DNU36)* JU63(DNU28)* JU65(DNU40)* JY60(DNU17)* JY62(DNU27)* JY66(DNU31)* KC68(DNU25)* KF62(DNU16)* KF64(DNU32)* KF70(DNU26)* LF10(NC6)* LF22(NC5)* LJ20(NC4)* LJ24(NC3)* MF2(NC2)* ML81(NC1)*; U14 3(P1_S0_IN_C)* 6(P1_S0_OUT_C) 7(P1_S0_OUT_D) 8(GPIO[2]) 10(P1_S1_IN_A)* 11(P1_S1_OUT_A)* 12(P1_S1_IN_B)* 13(P1_S1_OUT_B)* 14(P1_S1_IN_C)* 15(P1_AUX_SCL)* 16(P1_AUX_SDA)* 17(P1_S1_OUT_C)* 18(P1_S1_OUT_D)* 19(GPIO[3]) 29(TEST_N)* 30(SPI_LED_SY_NC)* 31(PROTOCOL_SEL)* 33(P0_S0_OUT_D) 34(P0_S0_OUT_C) 37(P0_S0_IN_C)* 42(GPIO[0]) 44(P0_S1_OUT_A)* 45(P0_S1_OUT_B)* 46(P0_S1_IN_C)* 47(P0_S1_IN_B)* 48(P0_AUX_SDA)* 49(P0_AUX_SCL)* 50(P0_S1_IN_A)* 51(P0_S1_OUT_C)* 52(P0_S1_OUT_D)* 53(GPIO[1]); U15 2(IOVL1) 3(IOVL2) 6(NC0)* 9(NC1)* 12(IOVCC2) 13(IOVCC1); U18 6(NC0)* 9(NC1)*

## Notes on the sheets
sheet 27
- Place a 1uF and 0.1uF per VDD2 pin
- Place a 1uF and 0.1uF per VDD1 pin
- I2C 8-bit Addr = 0x1E
sheet 28
- F-TILE BANK 12A
- Connect pin DY73 and EC74 to ground per PCG document
- ( To be updated in future board revision)
- Layout Note: place the res under BGA ball
sheet 29
- F-TILE BANK 12A DNU
- TRSTn
- Note: IO_DFX_0 = GND, disable FHT
sheet 30
- PCIe Endpoint Edge Connector
- Notes: Close --> select;
         Open --> deselect
- PCIe TX/RX signal naming convention
  with respect to CPU
- PCIE TX to FPGA RX
  P/N Lane Reversal during layout is allowed
- PCIE RX from FPGA TX
  P/N Lane Reversal during layout is allowed
- move R794 to near U26 or U30
  for easy power split of 3p3V_STBY
- Note: Place near to golden finger
- FRUID
- Addr = A0h
- 400Khz max
sheet 31
- R-TILE BANK 14C
sheet 32
- CXL Connector
- Design Note:
  Clock for RootPort mode.
- Design Note:
  Clock for RootPort mode.
